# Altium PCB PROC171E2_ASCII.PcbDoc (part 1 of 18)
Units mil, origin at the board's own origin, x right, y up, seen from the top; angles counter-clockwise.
Board outline 7700 x 2300 mil, 6 copper layers (Top Layer, GND 1, SIG 1, SIG 2, GND 2, Bottom Layer), stack 61.062 mil thick; 938 components, 688 nets, 11933 pads, 1723 vias.
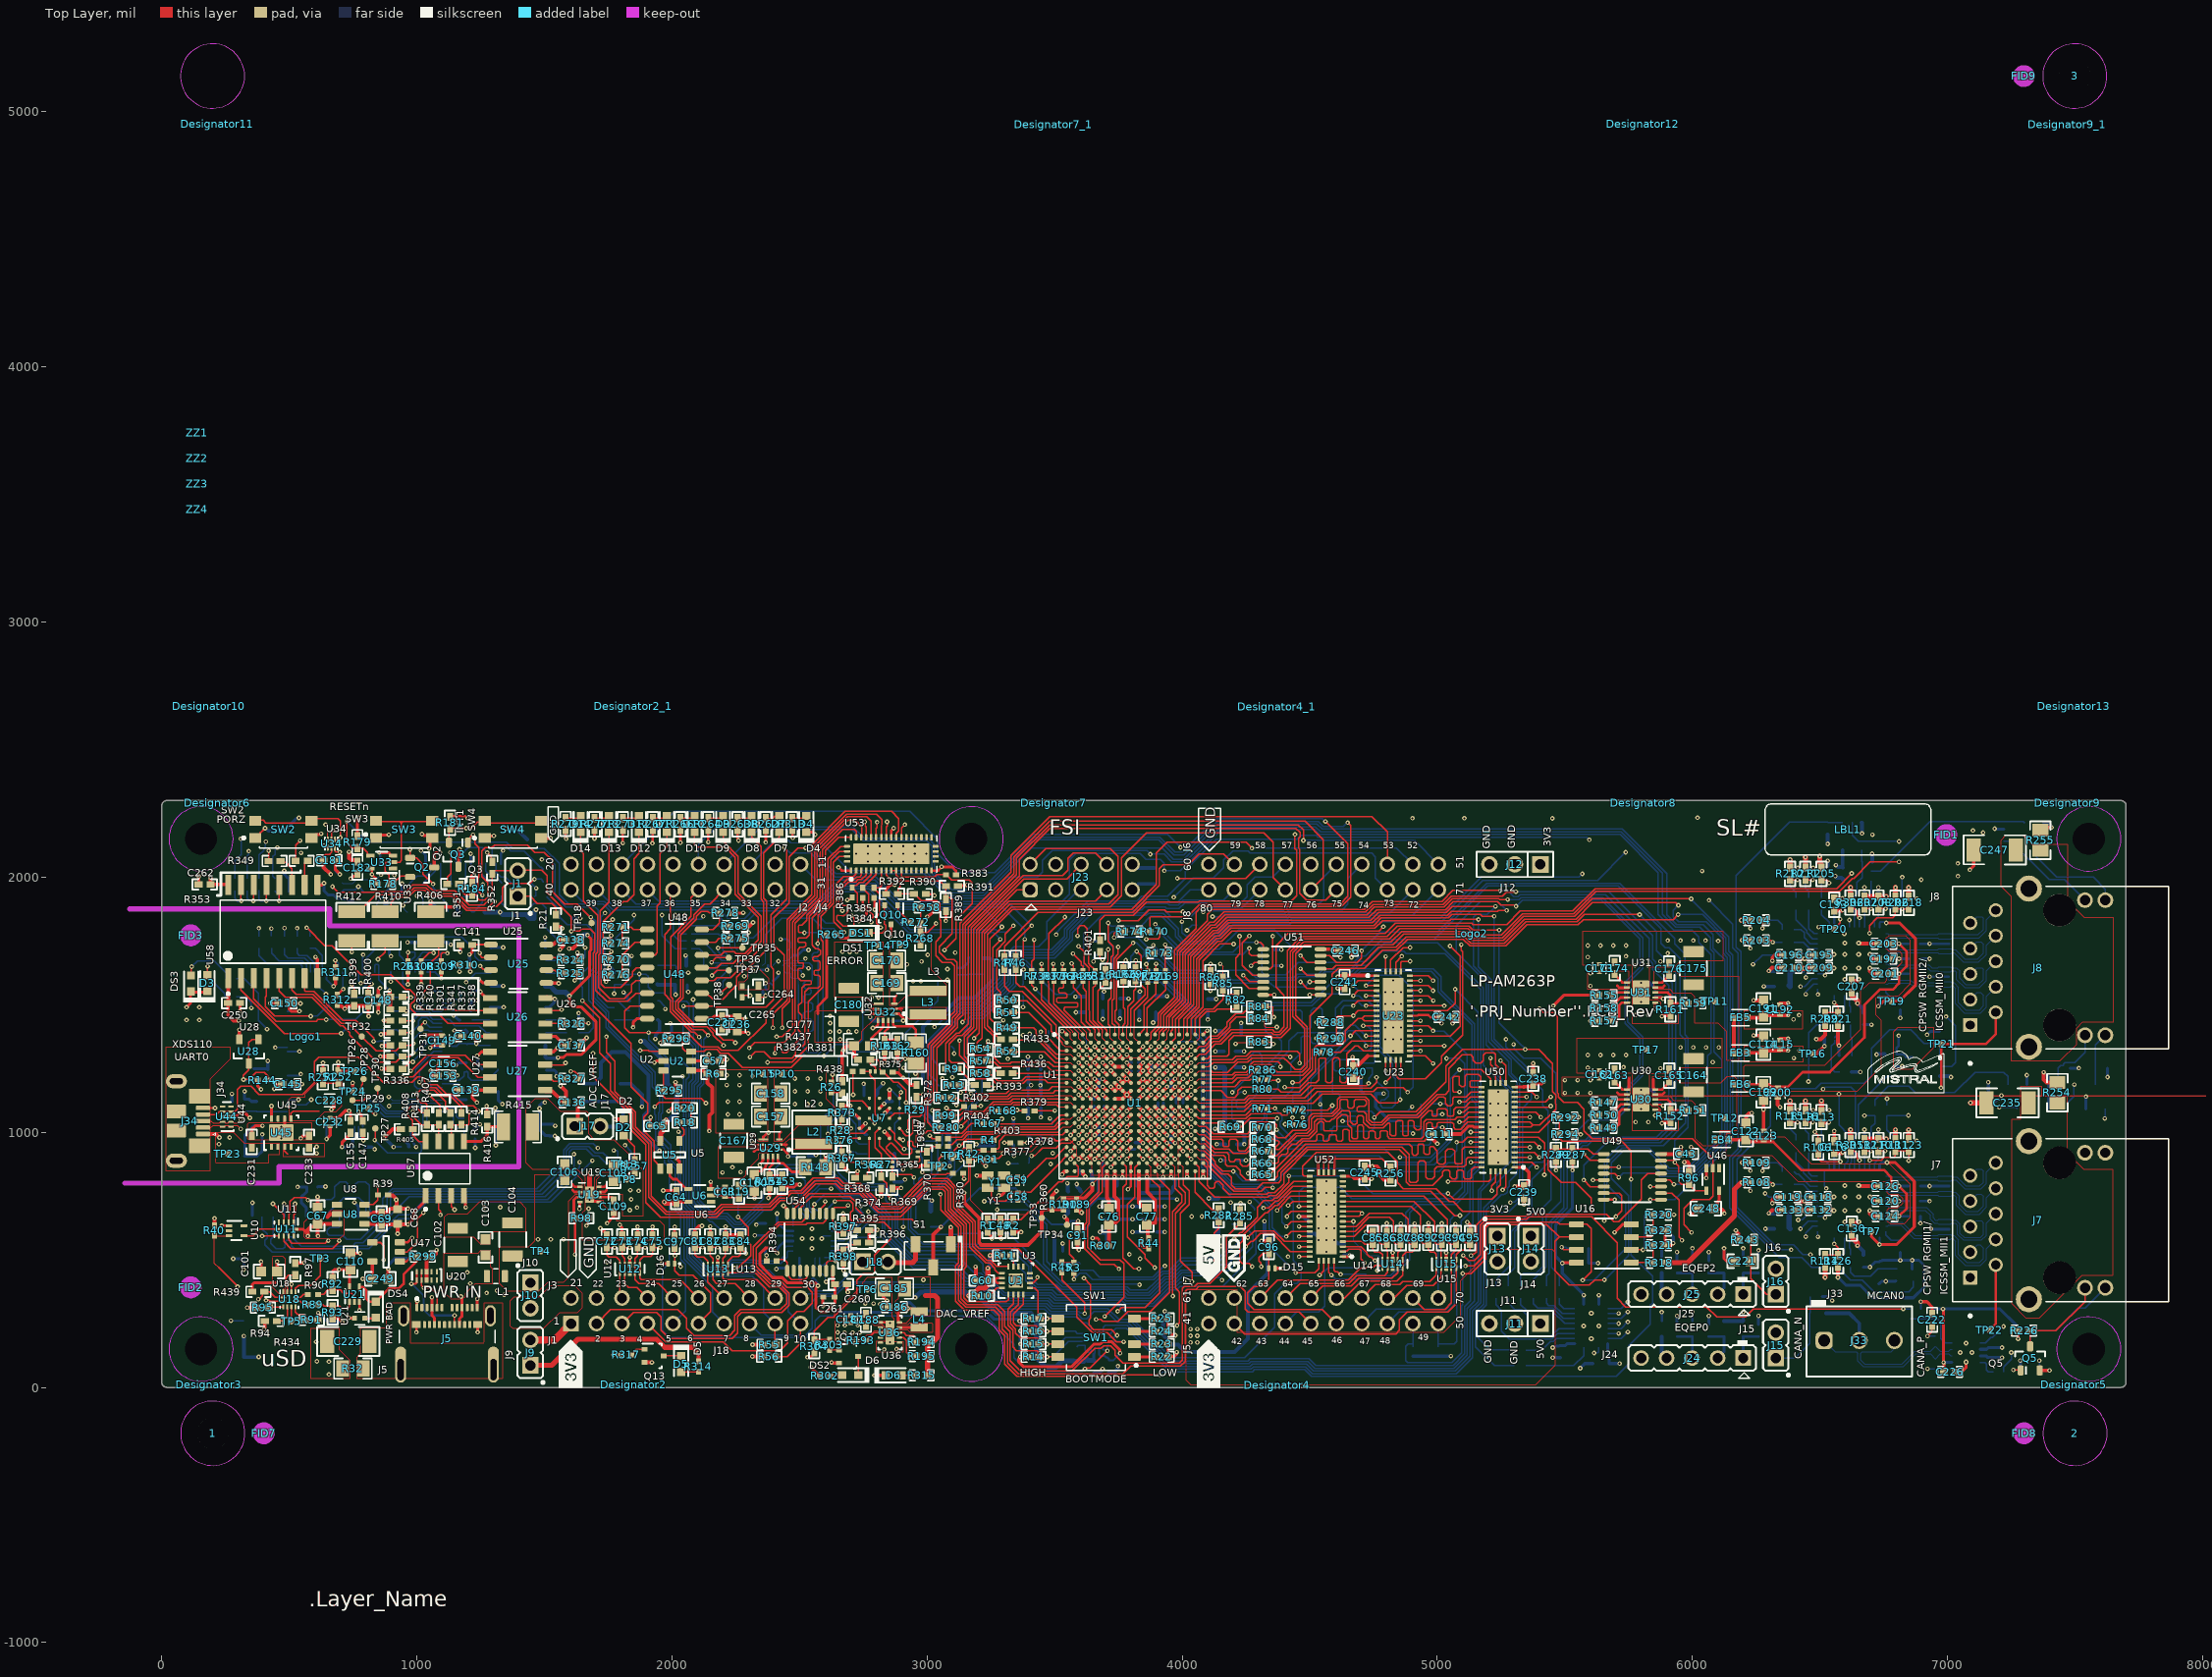
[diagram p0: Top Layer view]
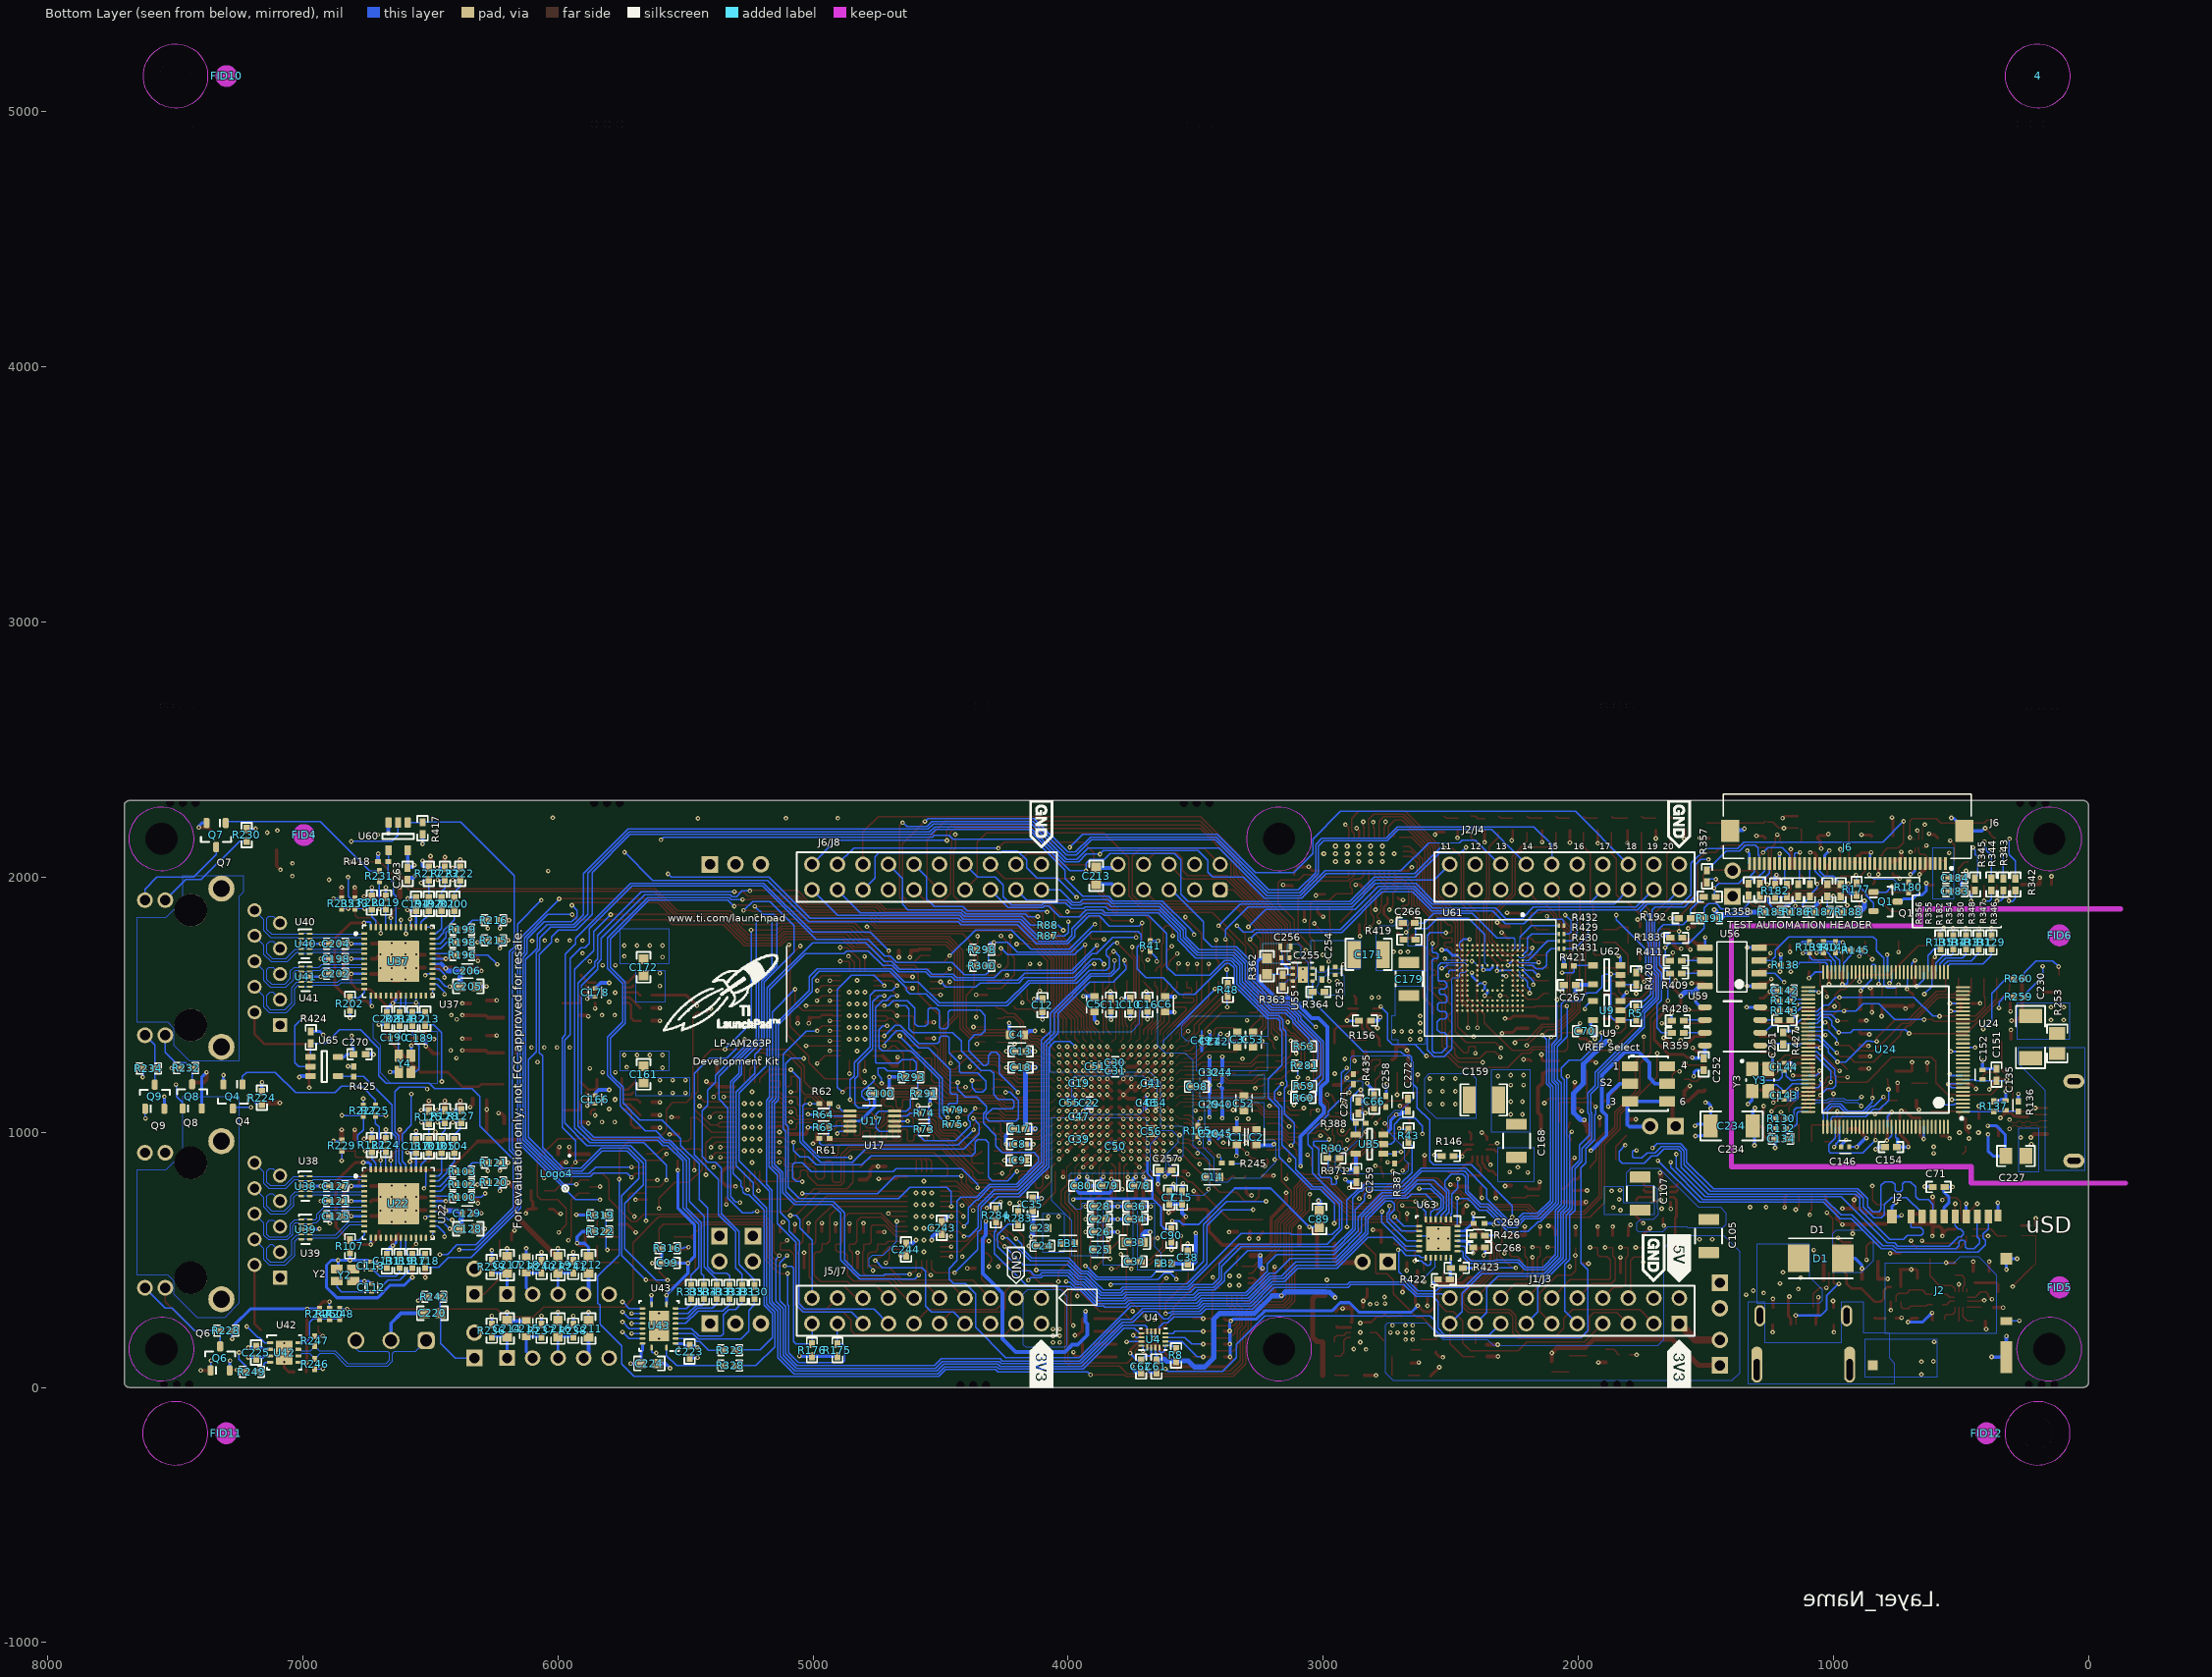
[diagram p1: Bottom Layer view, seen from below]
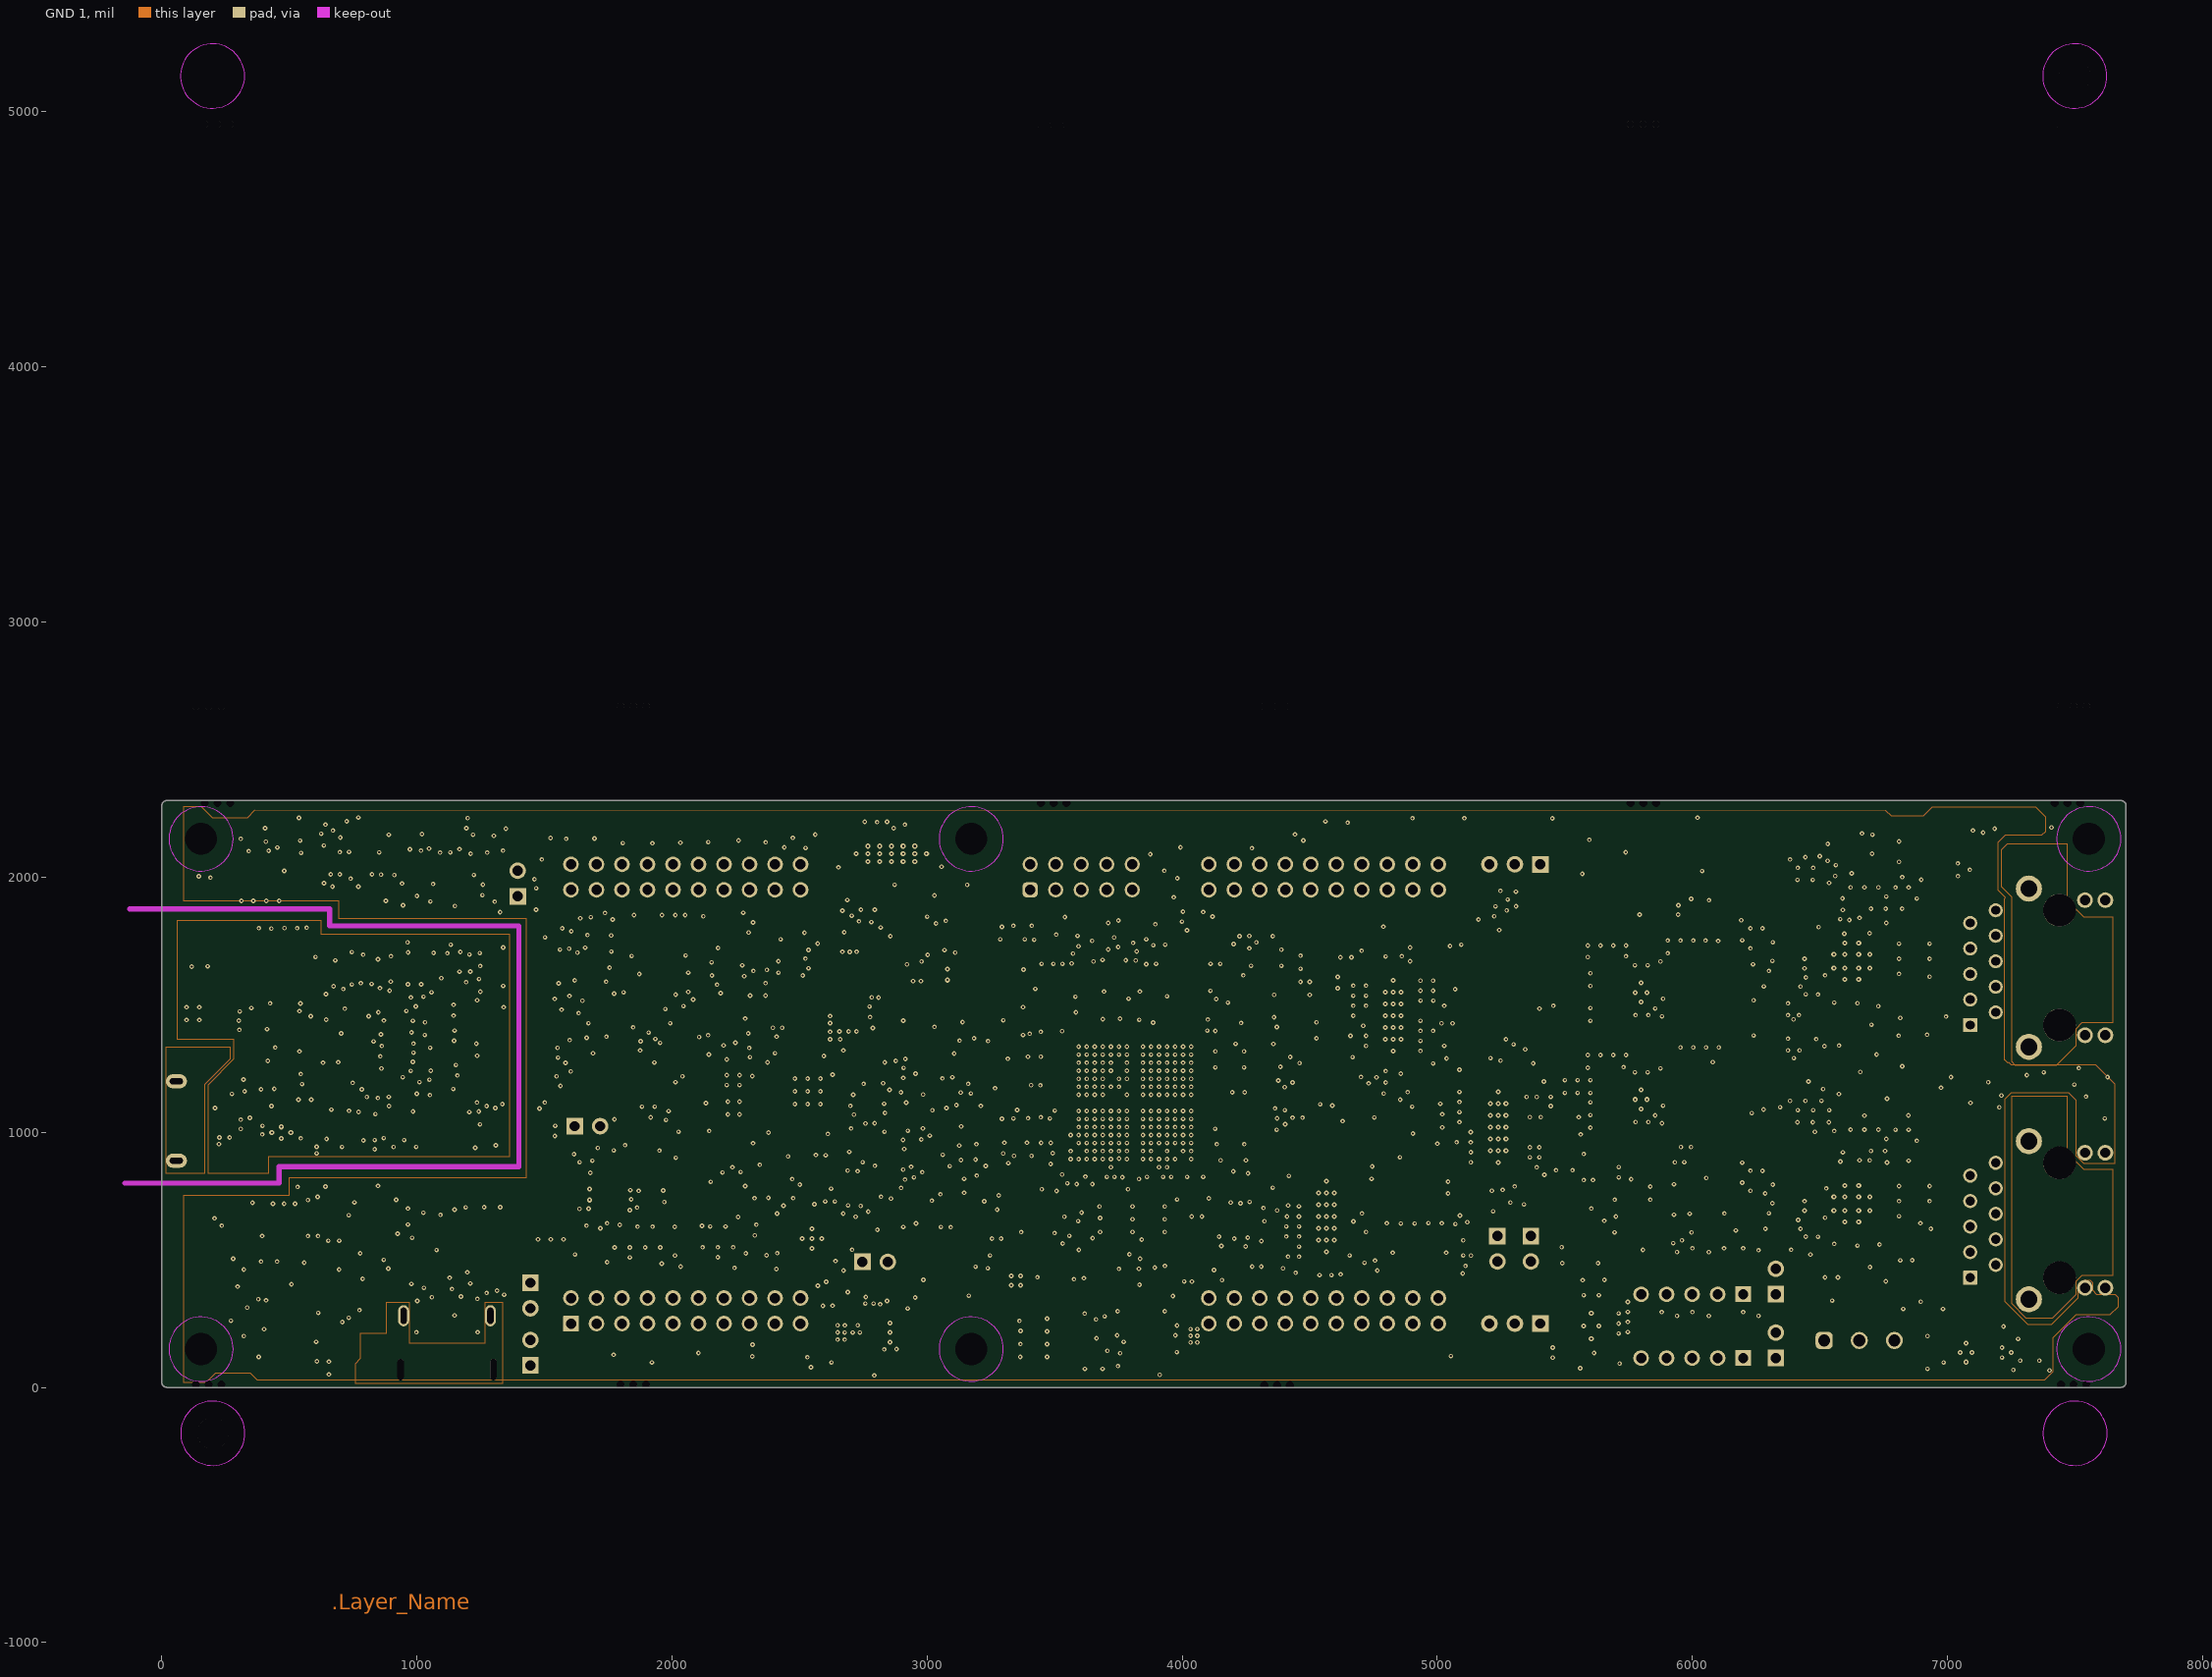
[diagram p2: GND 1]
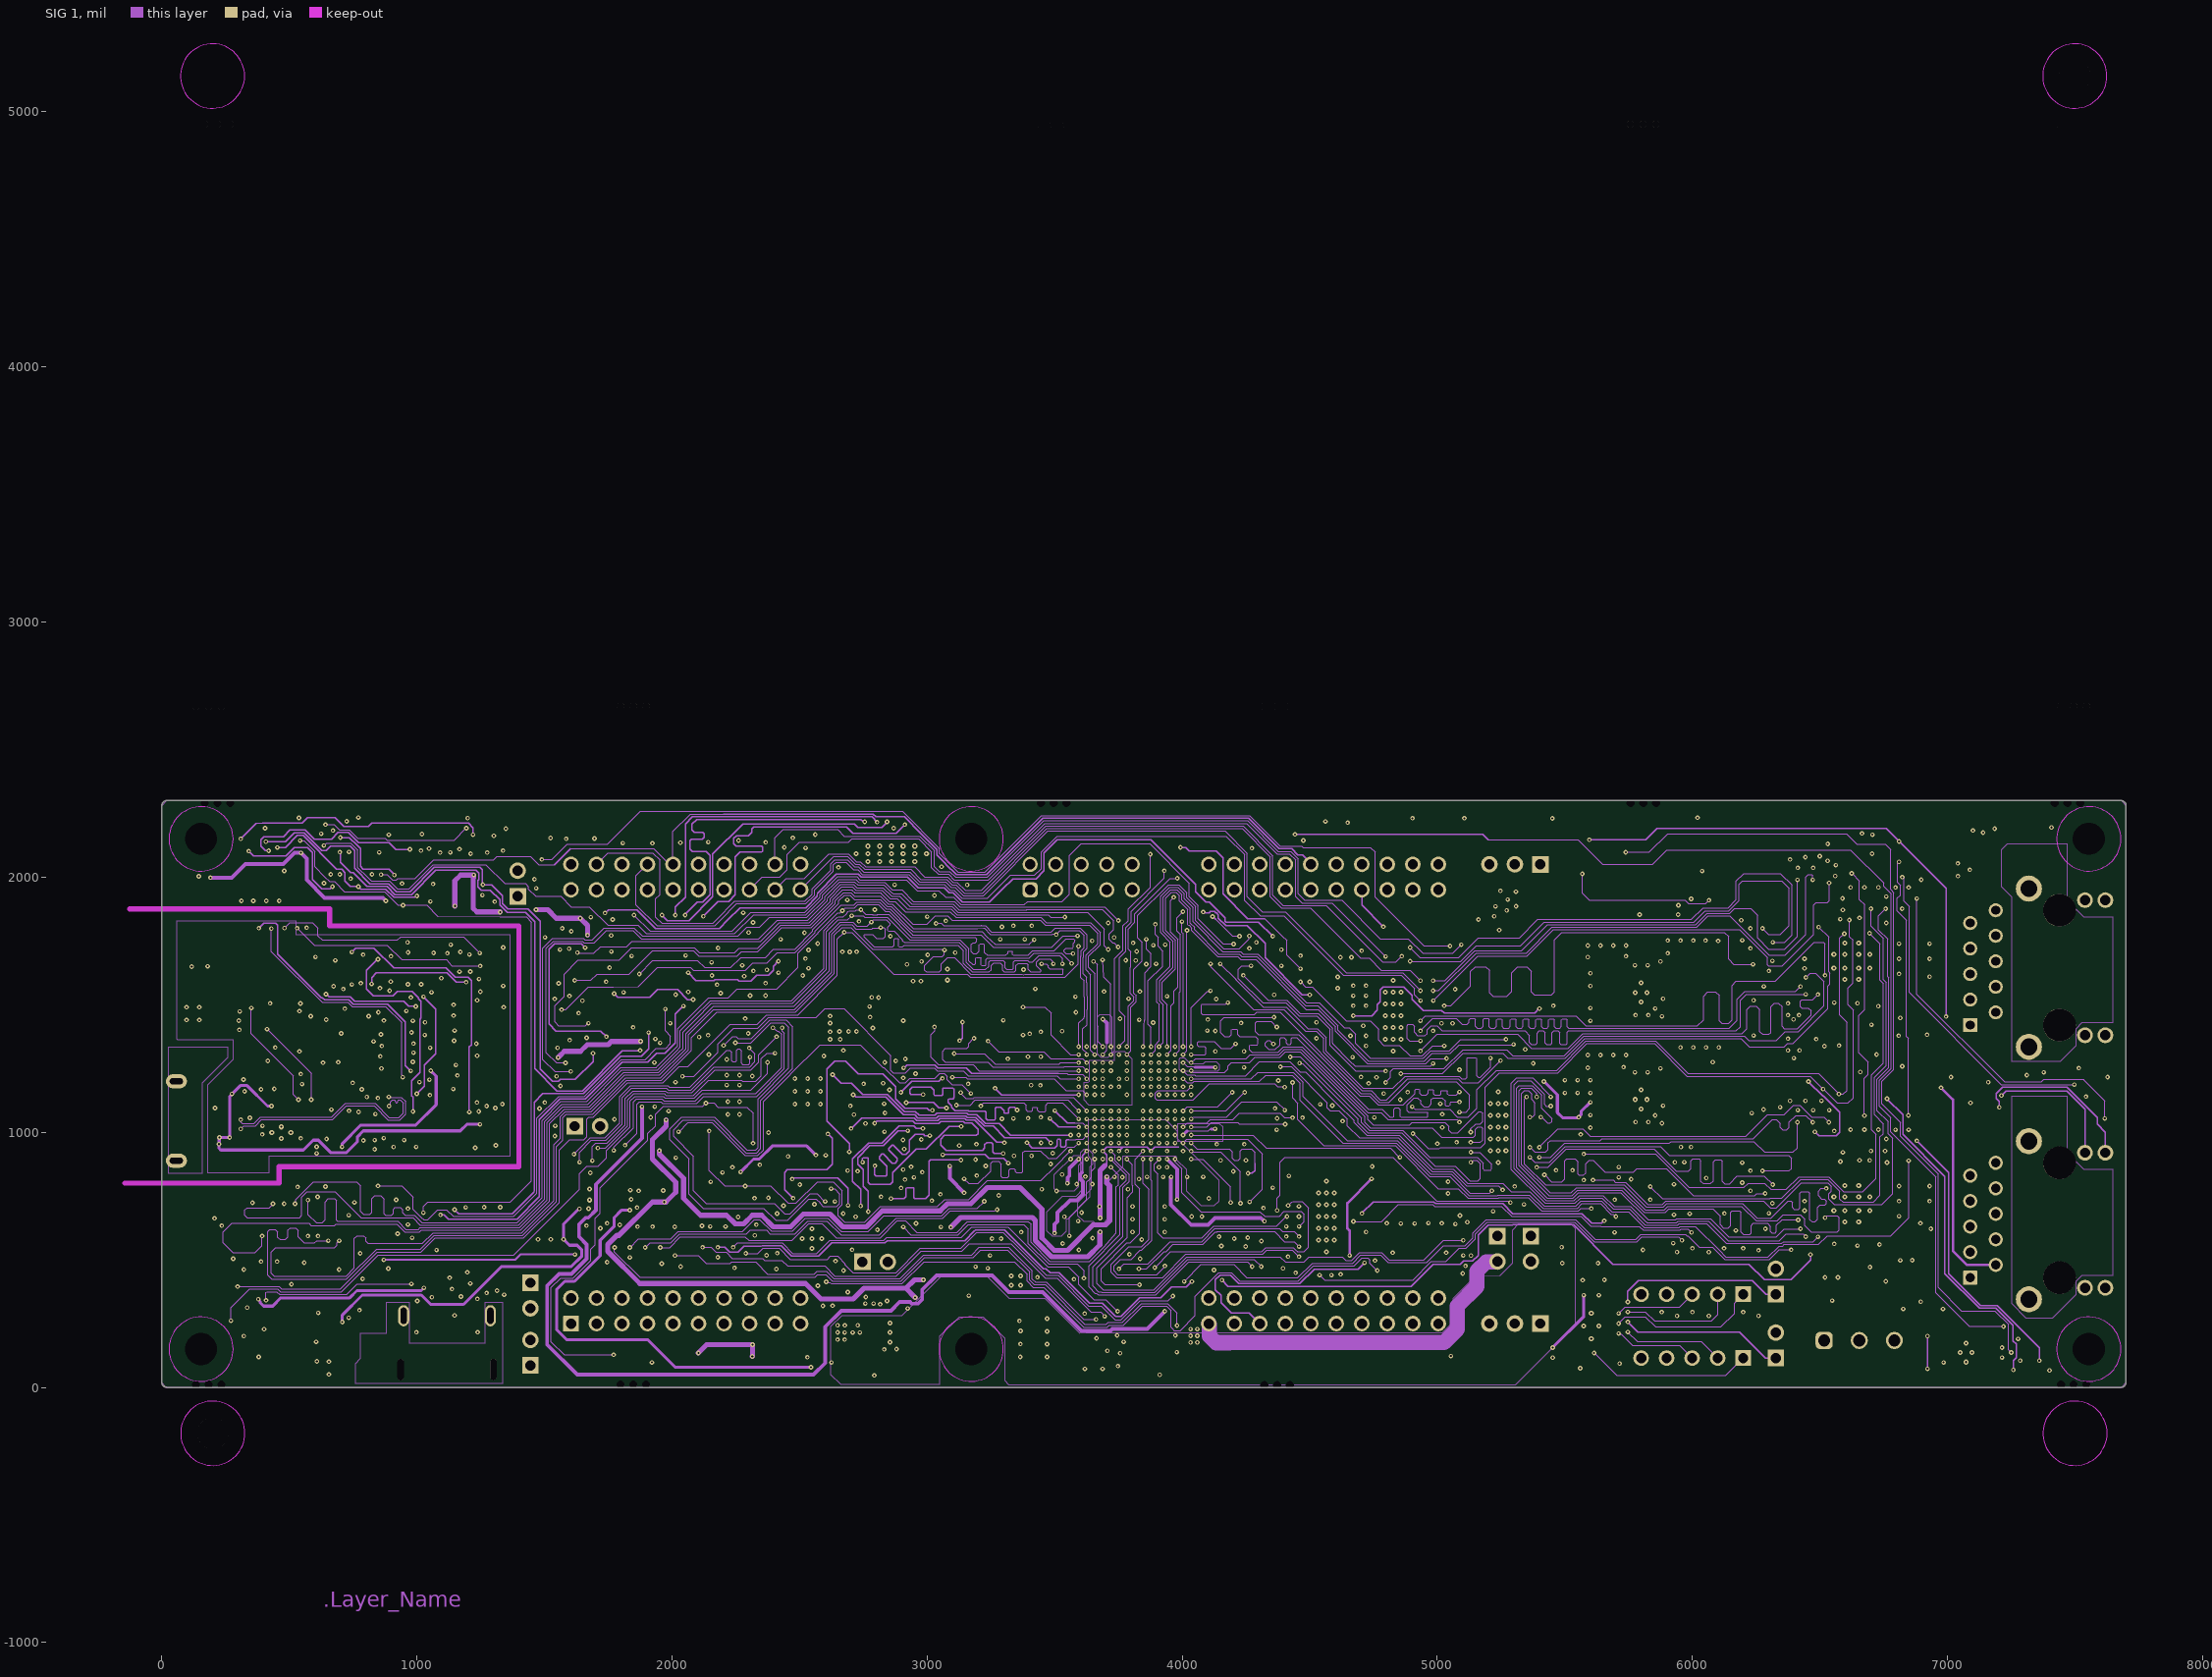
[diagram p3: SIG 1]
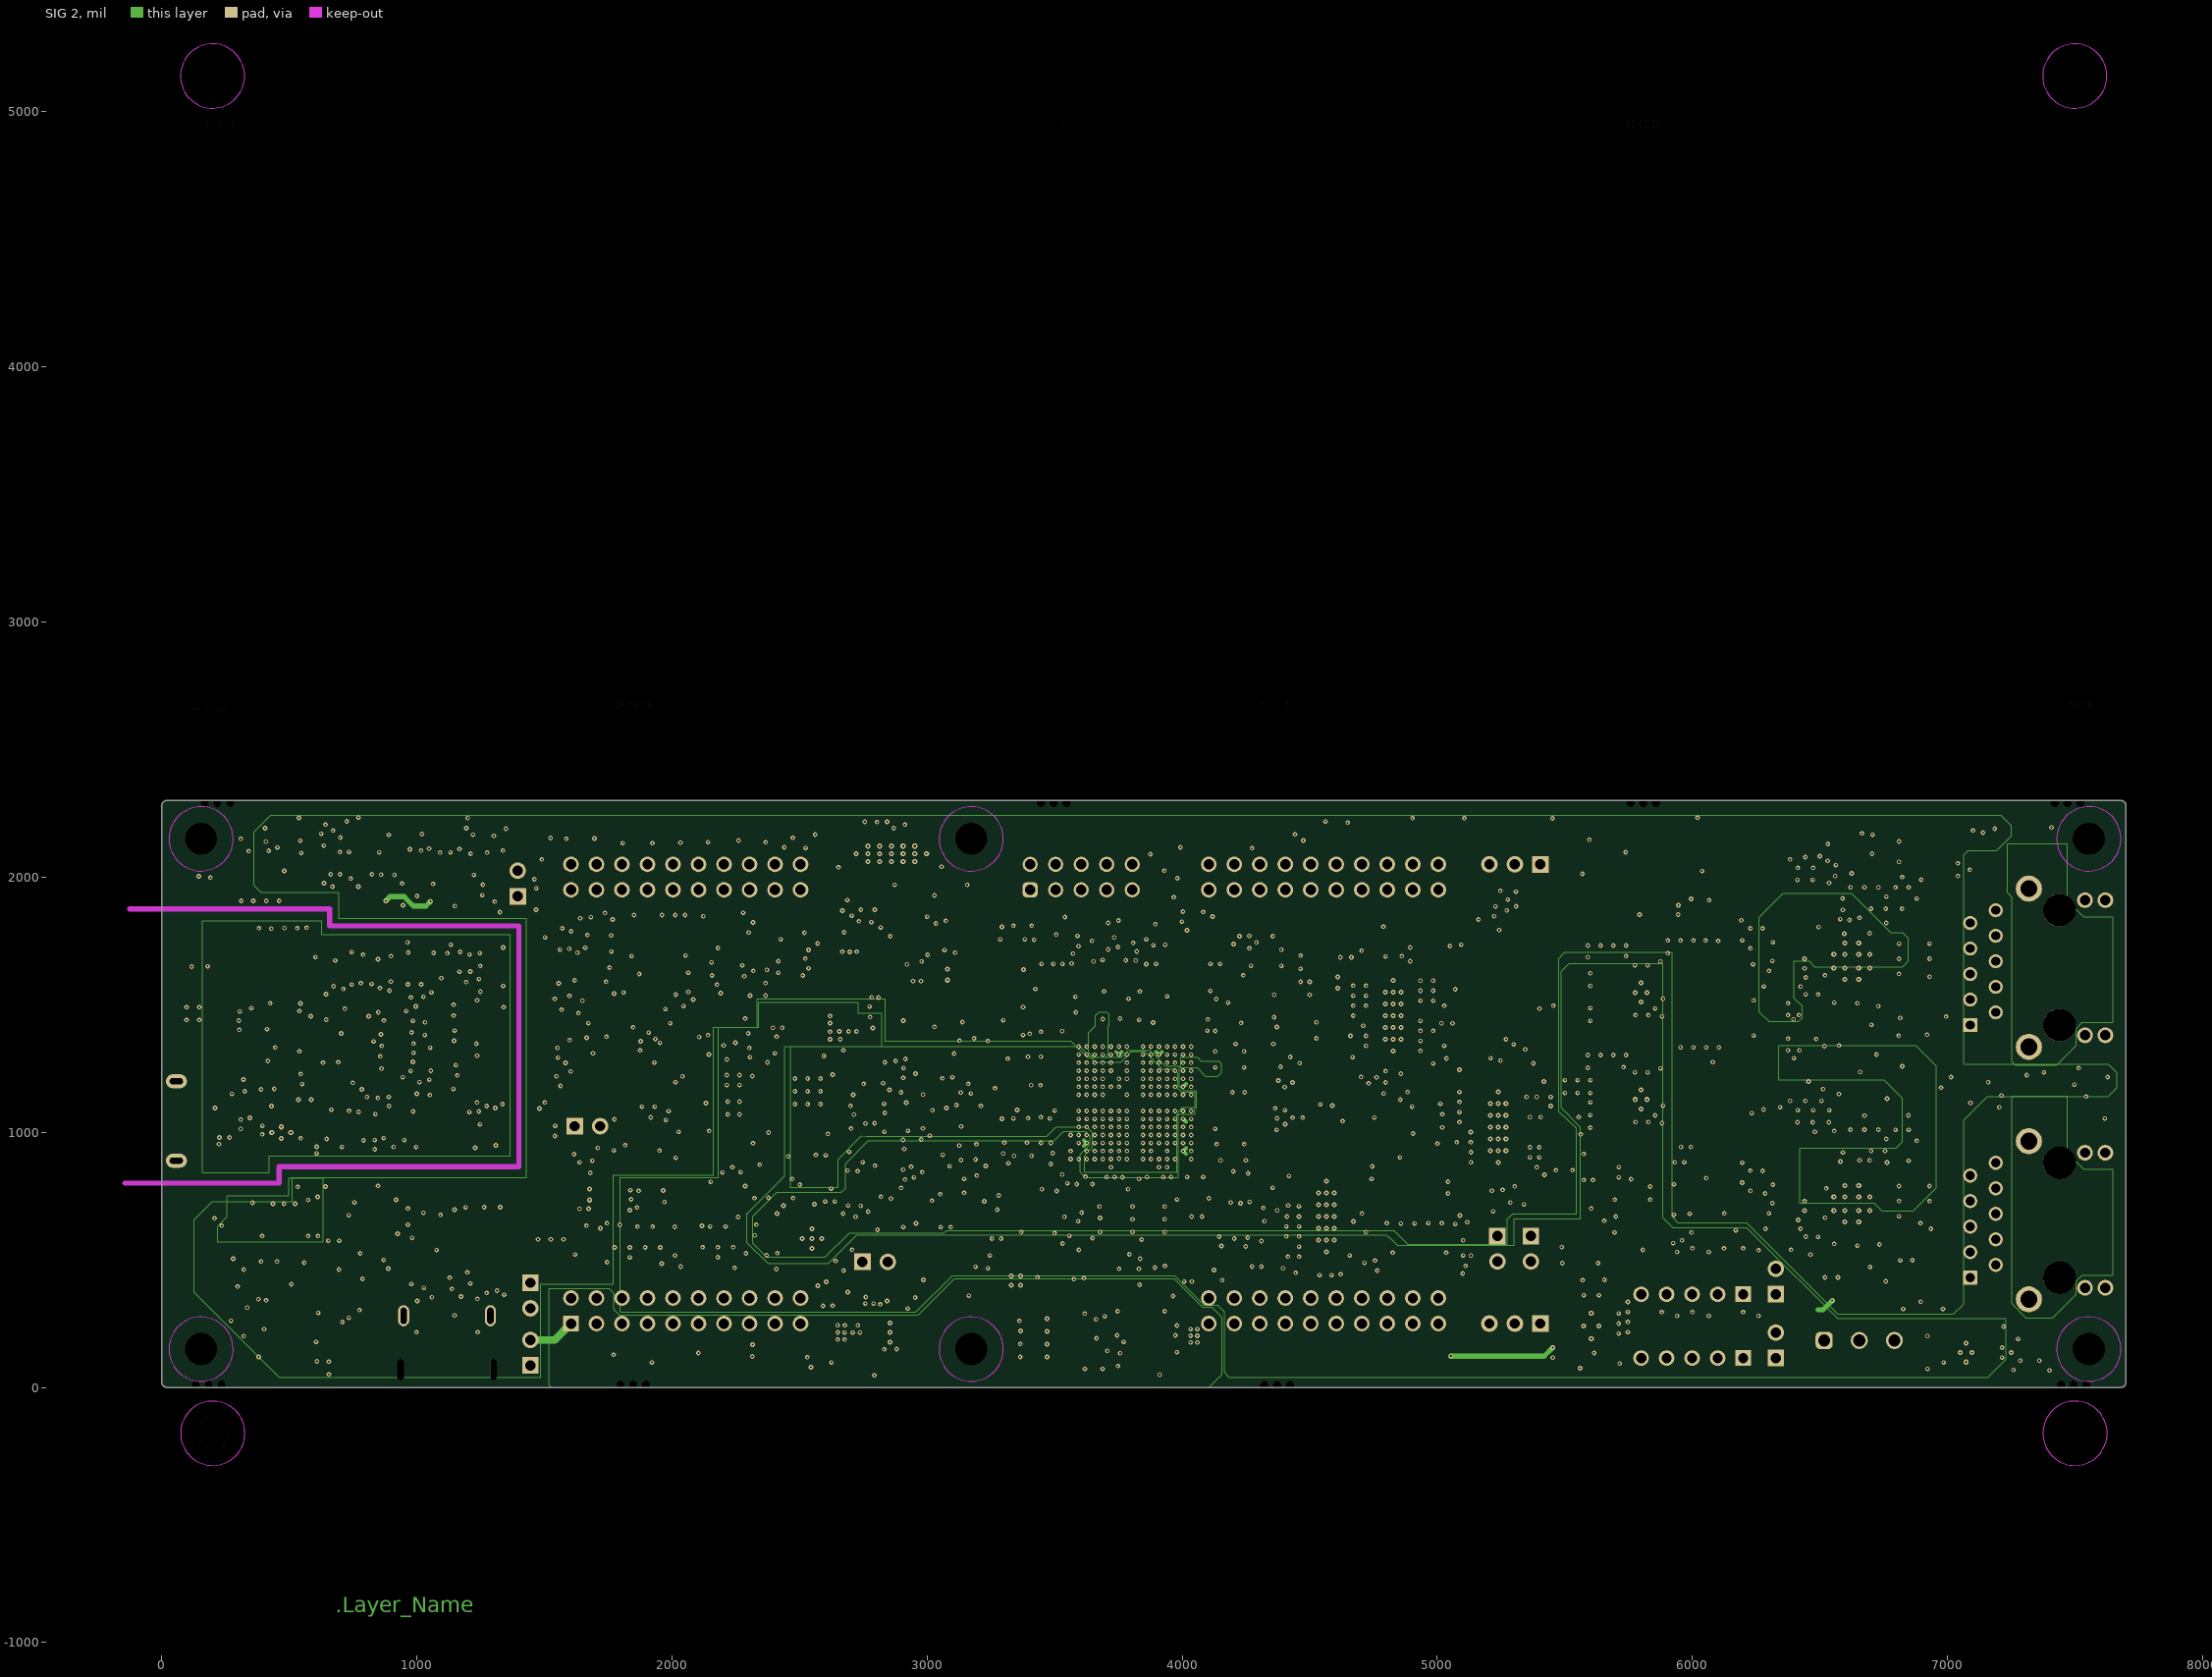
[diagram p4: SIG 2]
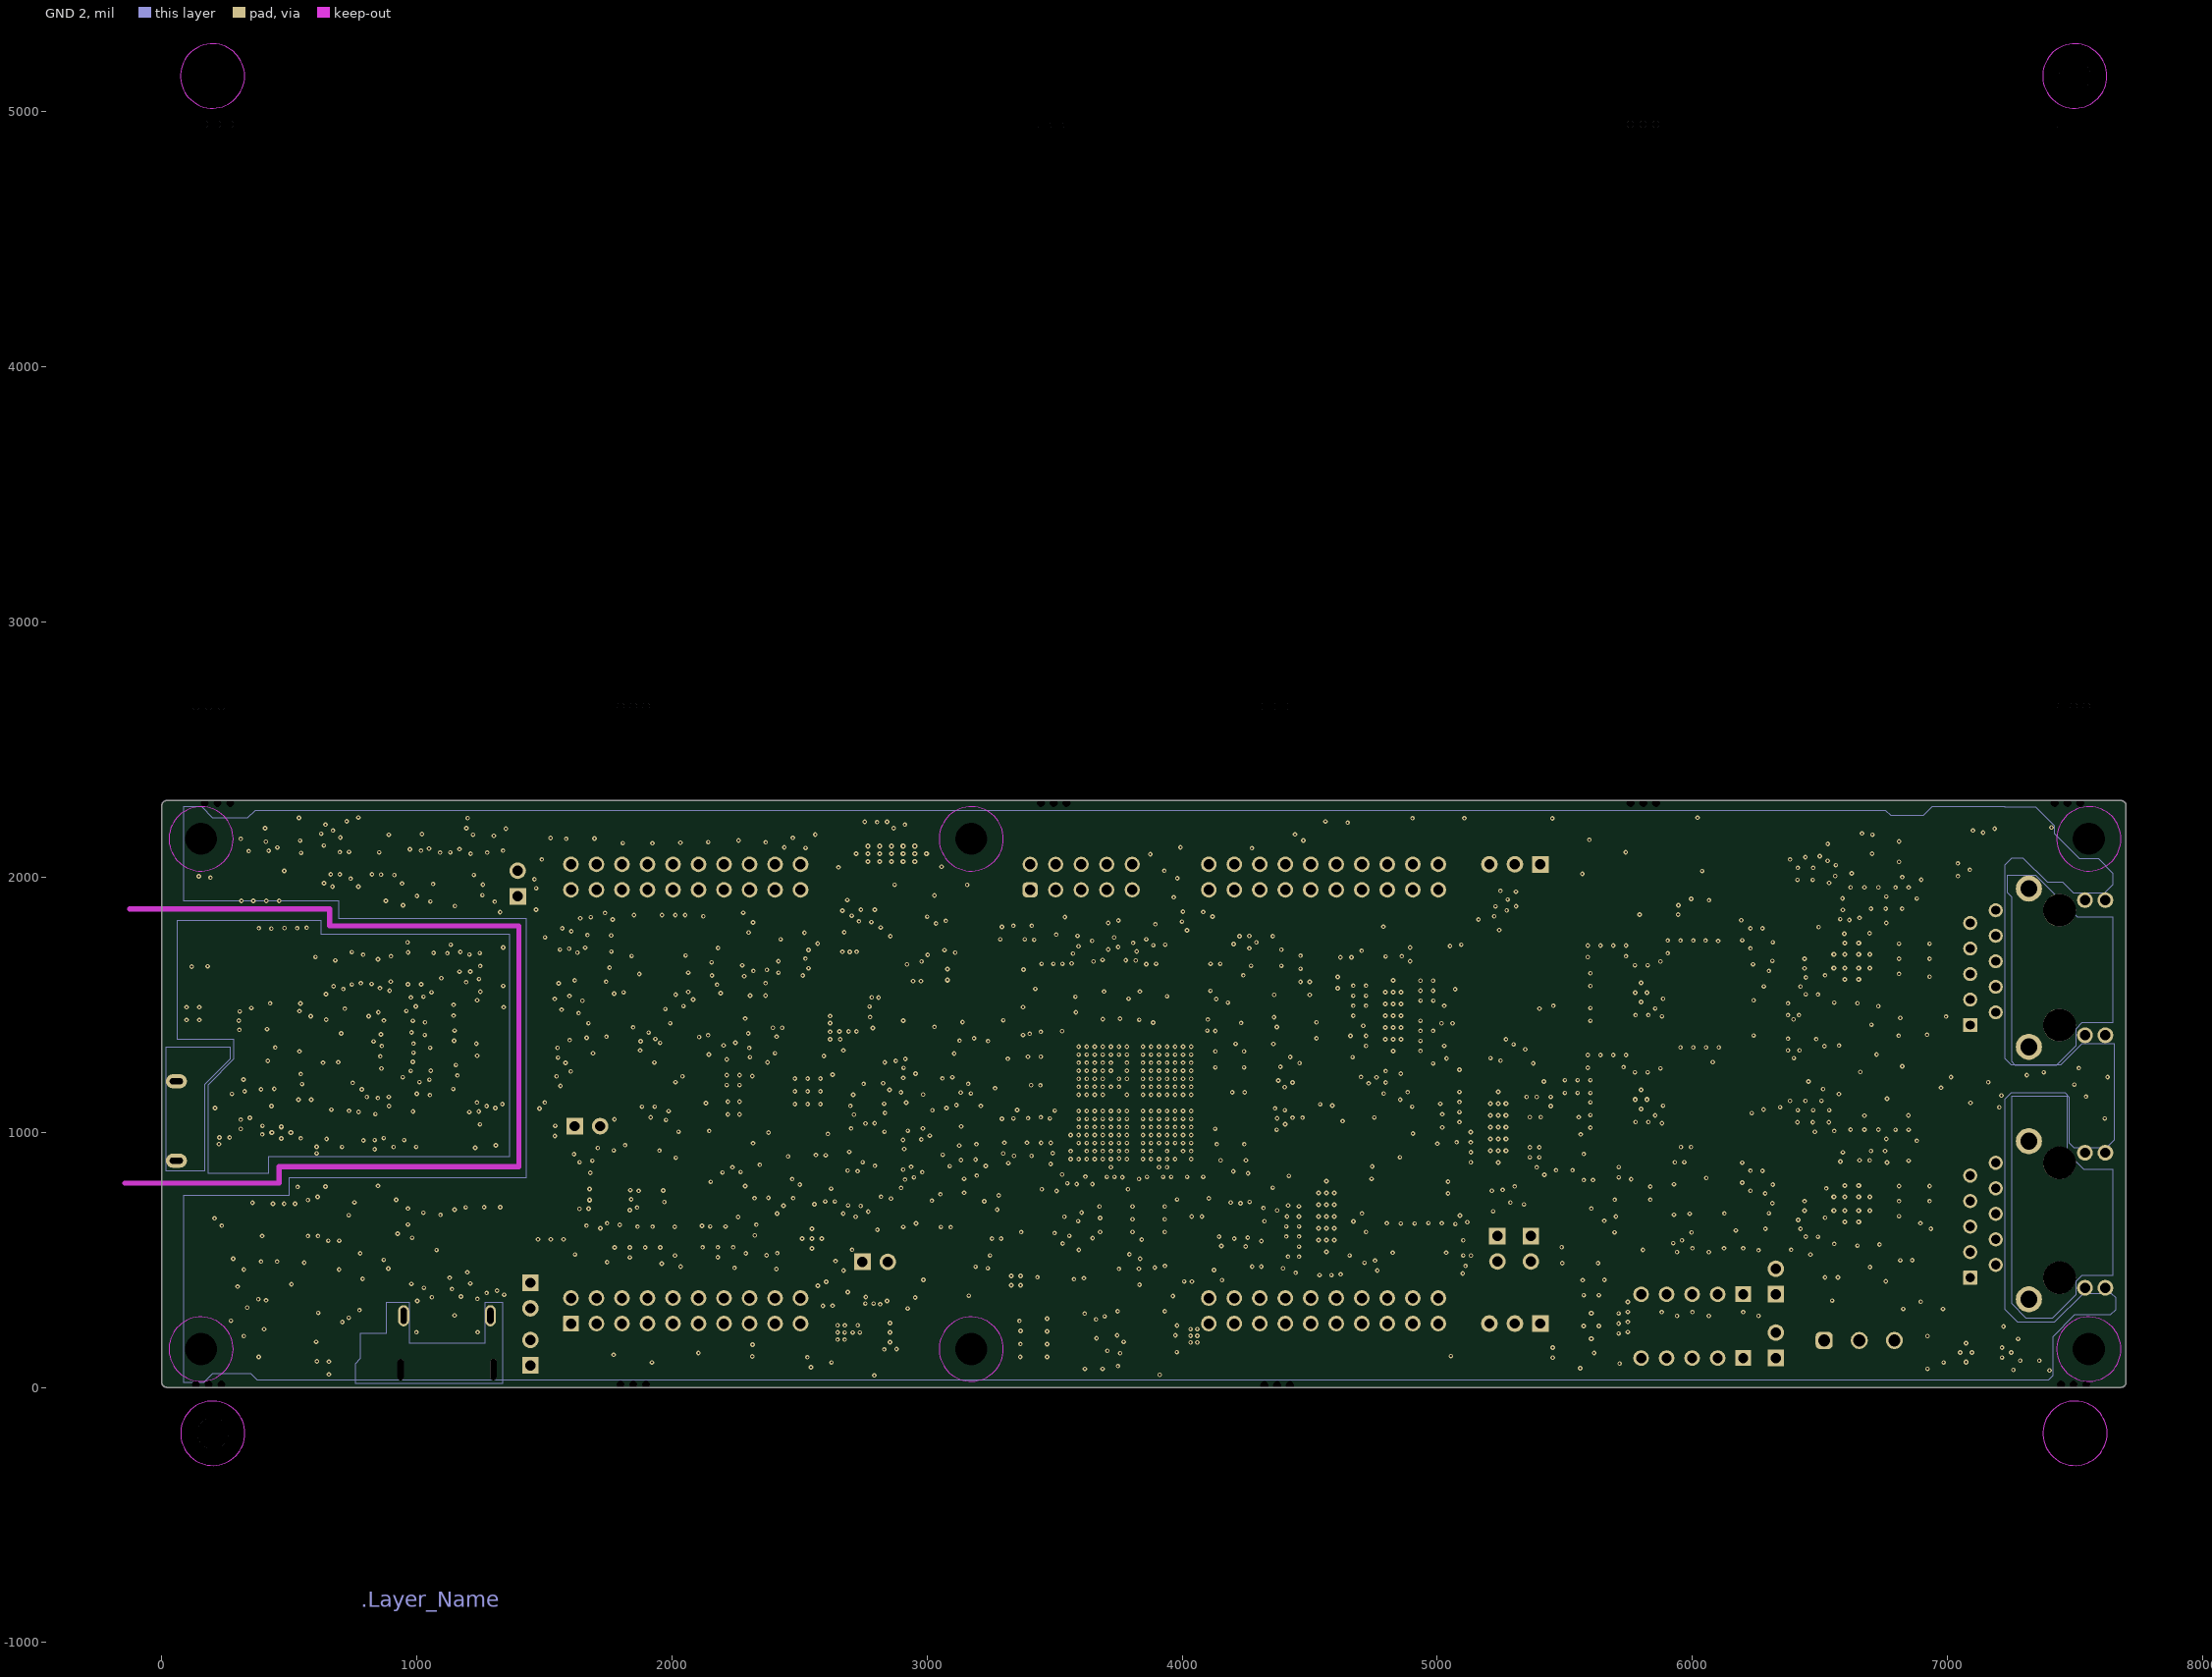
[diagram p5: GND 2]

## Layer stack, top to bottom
Top Solder: solder mask 1, Taiyo PSR 4000 HFX DI-GREEN, Dk 3.5
Top Layer: signal copper 2.087
Dielectric 1: prepreg 3.511, Iteq IT180A Prepreg 2113 RC58, Dk 4.13
GND 1: signal copper 1.26
Dielectric 3: core 4, Iteq IT180A 4 mil core 1/1, Dk 4.4
SIG 1: signal copper 1.26
Dielectric 5: core 1.75, Composite dielectric, Dk 3.79
Dielectric 6: core 2.663, Composite dielectric, Dk 3.79
Dielectric1: core 28, Composite dielectric, Dk 3.79
Dielectric 7: core 2.663, Composite dielectric, Dk 3.79
Dielectric 8: core 1.75, Composite dielectric, Dk 3.79
SIG 2: signal copper 1.26
Dielectric 4: core 4, Iteq IT180A 4 mil core 1/1, Dk 4.4
GND 2: signal copper 1.26
Dielectric 2: prepreg 3.511, Iteq IT180A Prepreg 2113 RC58, Dk 4.13
Bottom Layer: signal copper 2.087
Bottom Solder: solder mask 1, Taiyo PSR 4000 HFX DI-GREEN, Dk 3.5

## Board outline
0,20 0,2280 cw(c20,2280) 20,2300 7680,2300 cw(c7680,2280) 7700,2280 7700,20 cw(c7680,20) 7680,0 20,0 cw(c20,20)

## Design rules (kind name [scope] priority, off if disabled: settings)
AssemblyTestPointUsage [All] p0: scope1count=1 scope1_0_kind=Board scope1_0_value=Board scope2count=1 scope2_0_kind=Board scope2_0_value=Board commentlength=0
AssemblyTestPointUsage [All] p1: valid=2
AssemblyTestpoint [All] p0: scope1count=1 scope1_0_kind=Board scope1_0_value=Board scope2count=1 scope2_0_kind=Board scope2_0_value=Board commentlength=0
BoardOutlineClearance [All] p0 off: scope1count=1 scope1_0_kind=Board scope1_0_value=Board scope2count=1 scope2_0_kind=Board scope2_0_value=Board commentlength=172 gap=40 // Protel DXP Scope 1 Expression Was: OnCopper and Not InComponentClass('Logo') and not InComponentClass('FiducialMark') and not InRegion(1000,500,4000,800) and not InPoly
BoardOutlineClearance BoardOutlineClearance_Poly [All] p0 off: scope1count=1 scope1_0_kind=Board scope1_0_value=Board scope2count=1 scope2_0_kind=Board scope2_0_value=Board commentlength=58 gap=25 // Protel DXP Scope 1 Expression Was: OnCopper and IsPoly
BoardOutlineClearance BoardOutlineClearance_MountingHoles [All] p0 off: scope1count=1 scope1_0_kind=Board scope1_0_value=Board scope2count=1 scope2_0_kind=Board scope2_0_value=Board commentlength=86 gap=39.37 // Protel DXP Scope 1 Expression Was: OnCopper and InComponentClass('Mounting Holes')
BoardOutlineClearance BoardOutlineClearance_MountingHoles [OnCopper and InComponentClass('Mounting Holes')] p1: gap=39.37 ignorepadtopadclearanceinfootprint=FALSE
BoardOutlineClearance BoardOutlineClearance_Poly [OnCopper and IsPoly] p2: gap=25 ignorepadtopadclearanceinfootprint=FALSE
BoardOutlineClearance [OnCopper and Not InComponentClass('Logo') and not InComponentClass('FiducialMark') and not InRegion(1000,500,4000,800) and not InPoly] p3: gap=40 ignorepadtopadclearanceinfootprint=FALSE
Clearance FLASH-4mil [All] p0 off: scope1count=1 scope1_0_kind=Board scope1_0_value=Board scope2count=1 scope2_0_kind=Board scope2_0_value=Board commentlength=83 gap=3 // Protel DXP Scope 1 Expression Was: WithinRoom('FLASH - NAND') and OnBottomLayer
Clearance ADC_SIG1 [All] p0: scope1count=1 scope1_0_kind=Layer scope1_0_value=MID1 scope2count=1 scope2_0_kind=NetClass scope2_0_value=ADC0 commentlength=0 gap=7.87
Clearance ADC_EXT [All] p0 off: scope1count=1 scope1_0_kind=Board scope1_0_value=Board scope2count=1 scope2_0_kind=NetClass scope2_0_value=ADC0 commentlength=88 gap=7.87 // Protel DXP Scope 1 Expression Was: (OnLayer('Top Layer') or OnLayer('Bottom Layer'))
Clearance DIff_spacing [All] p0 off: scope1count=1 scope1_0_kind=Board scope1_0_value=Board scope2count=1 scope2_0_kind=Board scope2_0_value=Board commentlength=70 gap=7.87 // Protel DXP Scope 2 Expression Was: InDifferentialPair('XDSET_1_D')
Clearance 100E_CLR_same [All] p0 off: scope1count=1 scope1_0_kind=Board scope1_0_value=Board scope2count=1 scope2_0_kind=Board scope2_0_value=Board commentlength=70 gap=7.87 // Protel DXP Scope 1 Expression Was: InDifferentialPairClass('100E')
Clearance 100E_CLR [All] p0 off: scope1count=1 scope1_0_kind=Board scope1_0_value=Board scope2count=1 scope2_0_kind=Board scope2_0_value=Board commentlength=70 gap=7.87 // Protel DXP Scope 1 Expression Was: InDifferentialPairClass('100E')
Clearance 4mil [All] p0 off: scope1count=1 scope1_0_kind=Board scope1_0_value=Board scope2count=1 scope2_0_kind=Board scope2_0_value=Board commentlength=69 gap=4 // Protel DXP Scope 1 Expression Was: WithinRoom('PROC111_Hardware')
Clearance [All] p0: scope1count=1 scope1_0_kind=Board scope1_0_value=Board scope2count=1 scope2_0_kind=Board scope2_0_value=Board commentlength=0 gap=7.87
Clearance Clearance_Poly [All] p0 off: scope1count=1 scope1_0_kind=Board scope1_0_value=Board scope2count=1 scope2_0_kind=Board scope2_0_value=Board commentlength=48 gap=10 // Protel DXP Scope 1 Expression Was: InPolygon
Clearance Clearance_Keepouts [All] p0 off: scope1count=1 scope1_0_kind=Board scope1_0_value=Board scope2count=1 scope2_0_kind=Board scope2_0_value=Board commentlength=48 gap=1 // Protel DXP Scope 1 Expression Was: IsKeepOut
Clearance FLASH-4mil [WithinRoom('FLASH - NAND') and OnBottomLayer] p1: gap=3 ignorepadtopadclearanceinfootprint=TRUE except(3.4: Arc-SMDPad Track-SMDPad; 15: Fill-Fill Fill-Poly Fill-Region Poly-Poly Poly-Region Region-Region)
Clearance Clearance_Keepouts [IsKeepOut] p2: gap=1 ignorepadtopadclearanceinfootprint=FALSE
Clearance 4mil [WithinRoom('PROC111_Hardware')] p3: gap=4 ignorepadtopadclearanceinfootprint=TRUE except(15: Fill-Fill Fill-Poly Fill-Region Poly-Poly Poly-Region Region-Region)
Clearance ADC_EXT [(OnLayer('Top Layer') or OnLayer('Bottom Layer')) vs InNetClass('ADC0')] p4: gap=7.87 ignorepadtopadclearanceinfootprint=TRUE except(6: Via-Fill Via-Poly Via-Region; 10.6: Arc-Arc Arc-Track Track-Track; 18: Via-Via; 25: Fill-Fill Fill-Poly Fill-Region Poly-Poly Poly-Region Region-Region)
Clearance ADC_SIG1 [OnLayer('SIG 1') vs InNetClass('ADC0')] p5: gap=7.87 ignorepadtopadclearanceinfootprint=TRUE except(6: Via-Fill Via-Poly Via-Region; 9.5: Arc-Arc Arc-Track Track-Track; 18: Via-Via; 25: Fill-Fill Fill-Poly Fill-Region Poly-Poly Poly-Region Region-Region)
Clearance 100E_CLR_same [InDifferentialPairClass('100E')] p6: gap=7.87 ignorepadtopadclearanceinfootprint=TRUE except(7.7: Arc-Arc Arc-Track Track-Track; 10: Via-Fill Via-Poly Via-Region; 18: Via-Via; 25: Fill-Fill Fill-Poly Fill-Region Poly-Poly Poly-Region Region-Region)
Clearance 100E_CLR [InDifferentialPairClass('100E')] p7: gap=7.87 ignorepadtopadclearanceinfootprint=TRUE except(6: Via-Fill Via-Poly Via-Region; 16.2: Arc-Arc Arc-Track Track-Track; 18: Via-Via; 25: Fill-Fill Fill-Poly Fill-Region Poly-Poly Poly-Region Region-Region)
Clearance Clearance_Poly [InPolygon] p8: gap=10 ignorepadtopadclearanceinfootprint=TRUE except(6: Via-Fill Via-Poly Via-Region; 8: SMDPad-Fill SMDPad-Poly SMDPad-Region THPad-Fill THPad-Poly THPad-Region; 20: Fill-Fill Fill-Poly Fill-Region Poly-Poly Poly-Region Region-Region)
Clearance DIff_spacing [All vs InDifferentialPair('XDSET_1_D')] p9: gap=7.87 ignorepadtopadclearanceinfootprint=TRUE except(5: Arc-Arc Arc-Track Track-Track; 6: Via-Fill Via-Poly Via-Region; 18: Via-Via; 25: Fill-Fill Fill-Poly Fill-Region Poly-Poly Poly-Region Region-Region)
Clearance [All] p10: gap=7.87 ignorepadtopadclearanceinfootprint=TRUE except(5.3: Arc-Arc Arc-Track Track-Track; 6: SMDPad-SMDPad Via-Fill Via-Poly Via-Region; 7.4: Arc-SMDPad Track-SMDPad; 12: Via-Via; 25: Fill-Fill Fill-Poly Fill-Region Poly-Poly Poly-Region Region-Region)
ComponentClearance [All] p0: scope1count=1 scope1_0_kind=Board scope1_0_value=Board scope2count=1 scope2_0_kind=Board scope2_0_value=Board commentlength=0 gap=15 collisioncheckmode=3
ComponentClearance ComponentClearance_THtoTH [All] p0 off: scope1count=1 scope1_0_kind=Board scope1_0_value=Board scope2count=1 scope2_0_kind=Board scope2_0_value=Board commentlength=54 gap=20 collisioncheckmode=3 // Protel DXP Scope 2 Expression Was: IsThruComponent
ComponentClearance ComponentClearance_THtoSMT [All] p0 off: scope1count=1 scope1_0_kind=Board scope1_0_value=Board scope2count=1 scope2_0_kind=Board scope2_0_value=Board commentlength=53 gap=30 collisioncheckmode=3 // Protel DXP Scope 2 Expression Was: IsSMTComponent
ComponentClearance ComponentClearance_SmallPassives [All] p0 off: scope1count=1 scope1_0_kind=Board scope1_0_value=Board scope2count=1 scope2_0_kind=Board scope2_0_value=Board commentlength=508 gap=10 collisioncheckmode=3 // Protel DXP Scope 2 Expression Was: HasFootprint('0201*') or HasFootprint('0402*') or HasFootprint('0508') or HasFootprint('0603*') or HasFootprint('0612') or HasFootprint('0805*') or HasFootprint('0815*') or HasFootprint('0830*') or HasFootprint('1206*') or HasFootprint('1210*') or HasFootprint('1808*') or HasFootprint('1812*') or HasFootprint('1825*') or HasFootprint('2010*') or HasFootprint('2220*') or HasFootprint('2225*') or HasFootprint('2512*') or HasFootprint('2728*') or HasFootprint('3518*')
ComponentClearance ComponentClearance_MountingHoles [All] p0: scope1count=1 scope1_0_kind=ComponentClass scope1_0_value="Mounting Holes" scope2count=1 scope2_0_kind=Board scope2_0_value=Board commentlength=0 gap=100 collisioncheckmode=3
ComponentClearance ComponentClearance_ScrewToNut [All] p0 off: scope1count=1 scope1_0_kind=Board scope1_0_value=Board scope2count=1 scope2_0_kind=Board scope2_0_value=Board commentlength=71 gap=5 collisioncheckmode=3 // Protel DXP Scope 2 Expression Was: (HasFootprint('Keystone_1902C'))
ComponentClearance ComponentClearance_Logo [All] p0: scope1count=1 scope1_0_kind=ComponentClass scope1_0_value=Logo scope2count=1 scope2_0_kind=Board scope2_0_value=Board commentlength=0 gap=30 collisioncheckmode=3
ComponentClearance ComponentClearance_Shunt [All] p0: scope1count=1 scope1_0_kind=ComponentClass scope1_0_value=Header scope2count=1 scope2_0_kind=ComponentClass scope2_0_value=Shunt commentlength=0 gap=0 collisioncheckmode=3
ComponentClearance ComponentClearance_MountingHoles_FiducialMarks [All] p0: scope1count=1 scope1_0_kind=ComponentClass scope1_0_value="Mounting Holes" scope2count=1 scope2_0_kind=ComponentClass scope2_0_value=FiducialMark commentlength=0 gap=50 collisioncheckmode=3
ComponentClearance ComponentClearance_MountingHoles_FiducialMarks [InComponentClass('Mounting Holes') vs InComponentClass('FiducialMark')] p1: gap=50 collisioncheckmode=3 verticalgap=10 showdistances=FALSE
ComponentClearance ComponentClearance_Shunt [InComponentClass('Header') vs InComponentClass('Shunt')] p2: gap=0 collisioncheckmode=3 verticalgap=0 showdistances=FALSE
ComponentClearance ComponentClearance_Logo [InComponentClass('Logo')] p3: gap=30 collisioncheckmode=3 verticalgap=10 showdistances=FALSE
ComponentClearance ComponentClearance_ScrewToNut [(HasFootprint('NY PMS 440 0025 PH')) vs (HasFootprint('Keystone_1902C'))] p4: gap=5 collisioncheckmode=3 verticalgap=10 showdistances=FALSE
ComponentClearance ComponentClearance_MountingHoles [InComponentClass('Mounting Holes')] p5: gap=100 collisioncheckmode=3 verticalgap=100000 showdistances=FALSE
ComponentClearance ComponentClearance_SmallPassives [HasFootprint('0201*') or HasFootprint('0402*') or HasFootprint('0508') or HasFootprint('0603*') or HasFootprint('0612') or HasFootprint('0805*') or HasFootprint('0815*') or HasFootprint('0830*') or HasFootprint('1206*') or HasFootprint('1210*') or HasFootprint('1808*') or HasFootprint('1812*') or HasFootprint('1825*') or HasFootprint('2010*') or HasFootprint('2220*') or HasFootprint('2225*') or HasFootprint('2512*') or HasFootprint('2728*') or HasFootprint('3518*') vs HasFootprint('0201*') or HasFootprint('0402*') or HasFootprint('0508') or HasFootprint('0603*') or HasFootprint('0612') or HasFootprint('0805*') or HasFootprint('0815*') or HasFootprint('0830*') or HasFootprint('1206*') or HasFootprint('1210*') or HasFootprint('1808*') or HasFootprint('1812*') or HasFootprint('1825*') or HasFootprint('2010*') or HasFootprint('2220*') or HasFootprint('2225*') or HasFootprint('2512*') or HasFootprint('2728*') or HasFootprint('3518*')] p6: gap=10 collisioncheckmode=3 verticalgap=10 showdistances=FALSE
ComponentClearance ComponentClearance_THtoSMT [IsThruComponent vs IsSMTComponent] p7: gap=30 collisioncheckmode=3 verticalgap=30 showdistances=FALSE
ComponentClearance ComponentClearance_THtoTH [IsThruComponent vs IsThruComponent] p8: gap=20 collisioncheckmode=3 verticalgap=30 showdistances=FALSE
ComponentClearance [All] p9: gap=15 collisioncheckmode=3 verticalgap=15 showdistances=TRUE
DiffPairsRouting 90E [All] p0 off: scope1count=1 scope1_0_kind=Board scope1_0_value=Board scope2count=1 scope2_0_kind=Board scope2_0_value=Board commentlength=70 // Protel DXP Scope 1 Expression Was: InDifferentialPair('XDSET_1_D')
DiffPairsRouting 120E [All] p0 off: scope1count=1 scope1_0_kind=Board scope1_0_value=Board scope2count=1 scope2_0_kind=Board scope2_0_value=Board commentlength=65 // Protel DXP Scope 1 Expression Was: InDifferentialPair('CANA')
DiffPairsRouting 100E_DIFF [All] p0 off: scope1count=1 scope1_0_kind=Board scope1_0_value=Board scope2count=1 scope2_0_kind=Board scope2_0_value=Board commentlength=70 // Protel DXP Scope 1 Expression Was: InDifferentialPairClass('100E')
DiffPairsRouting 90E [InDifferentialPair('XDSET_1_D')] p1: maxlimit=10 minlimit=5 mostfreqgap=10 toplayer_prefgap=5 toplayer_minwidth=4.2 toplayer_maxwidth=15 toplayer_prefwidth=4.2 midlayer1_mingap=6 midlayer1_maxgap=6 midlayer1_prefgap=6 midlayer1_minwidth=4 midlayer1_maxwidth=4 midlayer1_prefwidth=4 midlayer2_mingap=10 midlayer2_minwidth=15 midlayer2_maxwidth=15 midlayer2_prefwidth=15 midlayer3_mingap=10 midlayer3_minwidth=15 midlayer3_maxwidth=15 midlayer3_prefwidth=15 midlayer4_mingap=10 midlayer4_minwidth=15 midlayer4_maxwidth=15 midlayer4_prefwidth=15 bottomlayer_prefgap=5 bottomlayer_minwidth=4.2 bottomlayer_maxwidth=15 bottomlayer_prefwidth=4.2 maxuncoupledlength=500
DiffPairsRouting 120E [InDifferentialPair('CANA')] p2: maxlimit=10 minlimit=6.8 mostfreqgap=10 toplayer_prefgap=6.8 toplayer_minwidth=4.1 toplayer_maxwidth=15 toplayer_prefwidth=4.1 midlayer1_mingap=10 midlayer1_minwidth=15 midlayer1_maxwidth=15 midlayer1_prefwidth=15 midlayer2_mingap=10 midlayer2_minwidth=15 midlayer2_maxwidth=15 midlayer2_prefwidth=15 midlayer3_mingap=10 midlayer3_minwidth=15 midlayer3_maxwidth=15 midlayer3_prefwidth=15 midlayer4_mingap=10 midlayer4_minwidth=15 midlayer4_maxwidth=15 midlayer4_prefwidth=15 bottomlayer_prefgap=6.8 bottomlayer_minwidth=4.1 bottomlayer_maxwidth=15 bottomlayer_prefwidth=4.1 maxuncoupledlength=500
DiffPairsRouting 100E_DIFF [InDifferentialPairClass('100E')] p3: maxlimit=100 minlimit=7.7 mostfreqgap=10 toplayer_maxgap=7.7 toplayer_prefgap=7.7 toplayer_minwidth=4 toplayer_maxwidth=4 toplayer_prefwidth=4 midlayer1_mingap=8.1 midlayer1_maxgap=8.1 midlayer1_prefgap=8.1 midlayer1_minwidth=3.5 midlayer1_maxwidth=3.5 midlayer1_prefwidth=3.5 midlayer2_mingap=10 midlayer2_minwidth=15 midlayer2_maxwidth=15 midlayer2_prefwidth=15 midlayer3_mingap=10 midlayer3_minwidth=15 midlayer3_maxwidth=15 midlayer3_prefwidth=15 midlayer4_mingap=10 midlayer4_minwidth=15 midlayer4_maxwidth=15 midlayer4_prefwidth=15 bottomlayer_maxgap=7.7 bottomlayer_prefgap=7.7 bottomlayer_minwidth=4 bottomlayer_maxwidth=4 bottomlayer_prefwidth=4 maxuncoupledlength=1000
FabricationTestPointUsage TestPointUsage [All] p0: scope1count=1 scope1_0_kind=Board scope1_0_value=Board scope2count=1 scope2_0_kind=Board scope2_0_value=Board commentlength=0 valid=2 allowmultiple=FALSE
FabricationTestPointUsage TestPointUsage [All] p1: valid=2 allowmultiple=FALSE
FabricationTestpoint Testpoint [All] p0: scope1count=1 scope1_0_kind=Board scope1_0_value=Board scope2count=1 scope2_0_kind=Board scope2_0_value=Board commentlength=0 side=3 testpointundercomponent=TRUE minsize=40 maxsize=100 preferedsize=60 minholesize=0 maxholesize=40 preferedholesize=32 testpointgrid=1
FabricationTestpoint Testpoint [All] p1: side=3 testpointundercomponent=TRUE minsize=40 maxsize=100 preferedsize=60 minholesize=0 maxholesize=40 preferedholesize=32 testpointgrid=1 allowsidetop=TRUE allowsidebottom=TRUE usegrid=TRUE gridtolerance=0.01
FanoutControl Fanout_Small [All] p0 off: scope1count=1 scope1_0_kind=Board scope1_0_value=Board scope2count=1 scope2_0_kind=Board scope2_0_value=Board commentlength=84 // Protel DXP Scope 1 Expression Was: (CompPinCount < 5)   Fanout_Small (Default Rule)
FanoutControl Fanout_Default [All] p0: scope1count=1 scope1_0_kind=Board scope1_0_value=Board scope2count=1 scope2_0_kind=Board scope2_0_value=Board commentlength=30 // Fanout_Default (Default Rule)
FanoutControl Fanout_SOIC [All] p0 off: scope1count=1 scope1_0_kind=Board scope1_0_value=Board scope2count=1 scope2_0_kind=Board scope2_0_value=Board commentlength=71 // Protel DXP Scope 1 Expression Was: IsSOIC   Fanout_SOIC (Default Rule)
FanoutControl Fanout_BGA [All] p0 off: scope1count=1 scope1_0_kind=Board scope1_0_value=Board scope2count=1 scope2_0_kind=Board scope2_0_value=Board commentlength=69 // Protel DXP Scope 1 Expression Was: IsBGA   Fanout_BGA (Default Rule)
FanoutControl Fanout_LCC [All] p0 off: scope1count=1 scope1_0_kind=Board scope1_0_value=Board scope2count=1 scope2_0_kind=Board scope2_0_value=Board commentlength=69 // Protel DXP Scope 1 Expression Was: IsLCC   Fanout_LCC (Default Rule)
FanoutControl Fanout_LCC [IsLCC] p1: bgadir=Out bgaviamode=Centered fanoutstyle=Auto fanoutdirection=Alternating viagrid=1 // Fanout_LCC (Default Rule)
FanoutControl Fanout_BGA [IsBGA] p2: bgadir=Out bgaviamode=Centered fanoutstyle=Auto fanoutdirection=Alternating viagrid=1 // Fanout_BGA (Default Rule)
FanoutControl Fanout_Default [All] p4: bgadir=Out bgaviamode=Centered fanoutstyle=Auto fanoutdirection=Alternating viagrid=1 // Fanout_Default (Default Rule)
FanoutControl Fanout_Small [(CompPinCount < 5)] p5: bgadir=Out bgaviamode=Centered fanoutstyle=Auto fanoutdirection=OutThenIn viagrid=1 // Fanout_Small (Default Rule)
Height [All] p0: scope1count=1 scope1_0_kind=Board scope1_0_value=Board scope2count=1 scope2_0_kind=Board scope2_0_value=Board commentlength=0
HoleSize [All] p0: scope1count=1 scope1_0_kind=Board scope1_0_value=Board scope2count=1 scope2_0_kind=Board scope2_0_value=Board commentlength=0 absolutevalues=TRUE maxlimit=251 minlimit=7.87 maxpercent=80.000 minpercent=20.000
HoleSize [All] p1: absolutevalues=TRUE maxlimit=251 minlimit=7.87 maxpercent=80.000 minpercent=20.000
HoleToHoleClearance [All] p0: scope1count=1 scope1_0_kind=Board scope1_0_value=Board scope2count=1 scope2_0_kind=Board scope2_0_value=Board commentlength=0
LayerPairs [All] p0: scope1count=1 scope1_0_kind=Board scope1_0_value=Board scope2count=1 scope2_0_kind=Board scope2_0_value=Board commentlength=0 enforce=TRUE
MatchedLengths PRO_PROU_GPIO(11-16) [All] p0 off: scope1count=1 scope1_0_kind=Board scope1_0_value=Board scope2count=1 scope2_0_kind=Board scope2_0_value=Board commentlength=77 tolerance=7.5 amplitude=200 gap=20 style=90-Degree // Protel DXP Scope 1 Expression Was: InxSignalClass('PRO_PROU_GPIO(11-16)')
MatchedLengths PRO_PROU_GPIO(0-6) [All] p0 off: scope1count=1 scope1_0_kind=Board scope1_0_value=Board scope2count=1 scope2_0_kind=Board scope2_0_value=Board commentlength=75 tolerance=7.5 amplitude=200 gap=20 style=90-Degree // Protel DXP Scope 1 Expression Was: InxSignalClass('PRO_PROU_GPIO(0-6)')
MatchedLengths AM263_RGMII1_RX [All] p0 off: scope1count=1 scope1_0_kind=Board scope1_0_value=Board scope2count=1 scope2_0_kind=Board scope2_0_value=Board commentlength=72 tolerance=7.5 amplitude=200 gap=20 style=90-Degree // Protel DXP Scope 1 Expression Was: InxSignalClass('AM263_RGMII1_RX')
MatchedLengths AM263_RGMII1_TX [All] p0 off: scope1count=1 scope1_0_kind=Board scope1_0_value=Board scope2count=1 scope2_0_kind=Board scope2_0_value=Board commentlength=72 tolerance=7.5 amplitude=200 gap=20 style=90-Degree // Protel DXP Scope 1 Expression Was: InxSignalClass('AM263_RGMII1_TX')
MatchedLengths ICSSM_MII1_RX [All] p0 off: scope1count=1 scope1_0_kind=Board scope1_0_value=Board scope2count=1 scope2_0_kind=Board scope2_0_value=Board commentlength=70 tolerance=7.5 amplitude=200 gap=20 style=90-Degree // Protel DXP Scope 1 Expression Was: InxSignalClass('ICSSM_MII1_RX')
MatchedLengths ICSSM_MII1_TX [All] p0 off: scope1count=1 scope1_0_kind=Board scope1_0_value=Board scope2count=1 scope2_0_kind=Board scope2_0_value=Board commentlength=70 tolerance=7.5 amplitude=200 gap=20 style=90-Degree // Protel DXP Scope 1 Expression Was: InxSignalClass('ICSSM_MII1_TX')
MatchedLengths ICSSM_MII0_TX [All] p0 off: scope1count=1 scope1_0_kind=Board scope1_0_value=Board scope2count=1 scope2_0_kind=Board scope2_0_value=Board commentlength=70 tolerance=7.5 amplitude=200 gap=20 style=90-Degree // Protel DXP Scope 1 Expression Was: InxSignalClass('ICSSM_MII0_TX')
MatchedLengths ICSSM_MII0_RX [All] p0 off: scope1count=1 scope1_0_kind=Board scope1_0_value=Board scope2count=1 scope2_0_kind=Board scope2_0_value=Board commentlength=70 tolerance=7.5 amplitude=200 gap=20 style=90-Degree // Protel DXP Scope 1 Expression Was: InxSignalClass('ICSSM_MII0_RX')
MatchedLengths ETH1_TX [All] p0 off: scope1count=1 scope1_0_kind=Board scope1_0_value=Board scope2count=1 scope2_0_kind=Board scope2_0_value=Board commentlength=64 tolerance=7.5 amplitude=200 gap=20 style=90-Degree // Protel DXP Scope 1 Expression Was: InxSignalClass('ETH1_TX')
MatchedLengths ETH1_RX [All] p0 off: scope1count=1 scope1_0_kind=Board scope1_0_value=Board scope2count=1 scope2_0_kind=Board scope2_0_value=Board commentlength=64 tolerance=7.5 amplitude=200 gap=20 style=90-Degree // Protel DXP Scope 1 Expression Was: InxSignalClass('ETH1_RX')
MatchedLengths DIFF [All] p0: scope1count=1 scope1_0_kind=Board scope1_0_value=Board scope2count=1 scope2_0_kind=Board scope2_0_value=Board commentlength=0 tolerance=2 amplitude=200 gap=20 style=90-Degree
MatchedLengths "SD CARD" [All] p0 off: scope1count=1 scope1_0_kind=Board scope1_0_value=Board scope2count=1 scope2_0_kind=Board scope2_0_value=Board commentlength=61 tolerance=25 amplitude=200 gap=20 style=90-Degree // Protel DXP Scope 1 Expression Was: InxSignalClass('MMC0')
MatchedLengths QSPI [All] p0 off: scope1count=1 scope1_0_kind=Board scope1_0_value=Board scope2count=1 scope2_0_kind=Board scope2_0_value=Board commentlength=67 tolerance=25 amplitude=200 gap=20 style=90-Degree // Protel DXP Scope 1 Expression Was: InxSignalClass('QSPI_FLASH')
MatchedLengths DIFF [All] p1: tolerance=2 checknetsindiffpair=TRUE checkdiffpairvsdiffpair=FALSE checkxsignals=FALSE checkothers=FALSE
MatchedLengths QSPI [InxSignalClass('QSPI_FLASH')] p2: tolerance=25 checknetsindiffpair=FALSE checkdiffpairvsdiffpair=TRUE checkxsignals=TRUE checkothers=TRUE
MatchedLengths ETH1_RX [InxSignalClass('ETH1_RX')] p3: tolerance=7.5 checknetsindiffpair=FALSE checkdiffpairvsdiffpair=TRUE checkxsignals=TRUE checkothers=TRUE
MatchedLengths ETH1_TX [InxSignalClass('ETH1_TX')] p4: tolerance=7.5 checknetsindiffpair=FALSE checkdiffpairvsdiffpair=TRUE checkxsignals=TRUE checkothers=TRUE
MatchedLengths ICSSM_MII0_RX [InxSignalClass('ICSSM_MII0_RX')] p5: tolerance=7.5 checknetsindiffpair=FALSE checkdiffpairvsdiffpair=TRUE checkxsignals=TRUE checkothers=TRUE
MatchedLengths AM263_RGMII1_TX [InxSignalClass('AM263_RGMII1_TX')] p6: tolerance=7.5 checknetsindiffpair=FALSE checkdiffpairvsdiffpair=TRUE checkxsignals=TRUE checkothers=TRUE
MatchedLengths PRO_PROU_GPIO(0-6) [InxSignalClass('PRO_PROU_GPIO(0-6)')] p7: tolerance=7.5 checknetsindiffpair=FALSE checkdiffpairvsdiffpair=TRUE checkxsignals=TRUE checkothers=TRUE
MatchedLengths PRO_PROU_GPIO(11-16) [InxSignalClass('PRO_PROU_GPIO(11-16)')] p8: tolerance=7.5 checknetsindiffpair=FALSE checkdiffpairvsdiffpair=TRUE checkxsignals=TRUE checkothers=TRUE
MatchedLengths AM263_RGMII1_RX [InxSignalClass('AM263_RGMII1_RX')] p9: tolerance=7.5 checknetsindiffpair=FALSE checkdiffpairvsdiffpair=TRUE checkxsignals=TRUE checkothers=TRUE
MatchedLengths ICSSM_MII0_TX [InxSignalClass('ICSSM_MII0_TX')] p10: tolerance=7.5 checknetsindiffpair=FALSE checkdiffpairvsdiffpair=TRUE checkxsignals=TRUE checkothers=TRUE
MatchedLengths ICSSM_MII1_TX [InxSignalClass('ICSSM_MII1_TX')] p11: tolerance=7.5 checknetsindiffpair=FALSE checkdiffpairvsdiffpair=TRUE checkxsignals=TRUE checkothers=TRUE
MatchedLengths ICSSM_MII1_RX [InxSignalClass('ICSSM_MII1_RX')] p12: tolerance=7.5 checknetsindiffpair=FALSE checkdiffpairvsdiffpair=TRUE checkxsignals=TRUE checkothers=TRUE
MatchedLengths "SD CARD" [InxSignalClass('MMC0')] p13: tolerance=25 checknetsindiffpair=FALSE checkdiffpairvsdiffpair=TRUE checkxsignals=TRUE checkothers=TRUE
MinimumAnnularRing [All] p0: scope1count=1 scope1_0_kind=Board scope1_0_value=Board scope2count=1 scope2_0_kind=Board scope2_0_value=Board commentlength=0 minimumring=5
MinimumAnnularRing MinimumAnnularRing_ThermalPadVias [All] p0 off: scope1count=1 scope1_0_kind=Board scope1_0_value=Board scope2count=1 scope2_0_kind=Board scope2_0_value=Board commentlength=63 minimumring=5.91 // Protel DXP Scope 1 Expression Was: IsVia and InAnyComponent
MinimumAnnularRing MinimumAnnularRing_ThermalPadVias [IsVia and InAnyComponent] p1: minimumring=5.91
MinimumAnnularRing [All] p2: minimumring=5
MinimumSolderMaskSliver MinimumSolderMaskSliver_Logo [All] p0: scope1count=1 scope1_0_kind=ComponentClass scope1_0_value=Logo scope2count=1 scope2_0_kind=ComponentClass scope2_0_value=Logo commentlength=0
MinimumSolderMaskSliver MinimumSolderMaskSliver_Logo [InComponentClass('Logo') vs InComponentClass('Logo')] p1: minsoldermaskwidth=0.7
NetAntennae [All] p0: scope1count=1 scope1_0_kind=Board scope1_0_value=Board scope2count=1 scope2_0_kind=Board scope2_0_value=Board commentlength=0
PasteMaskExpansion [All] p0: scope1count=1 scope1_0_kind=Board scope1_0_value=Board scope2count=1 scope2_0_kind=Board scope2_0_value=Board commentlength=0 expansion=0
PlaneClearance [All] p0: scope1count=1 scope1_0_kind=Board scope1_0_value=Board scope2count=1 scope2_0_kind=Board scope2_0_value=Board commentlength=0 clearance=20
PlaneConnect [All] p0: scope1count=1 scope1_0_kind=Board scope1_0_value=Board scope2count=1 scope2_0_kind=Board scope2_0_value=Board commentlength=0 planeconnectstyle=Direct reliefexpansion=10 reliefentries=4 reliefconductorwidth=10 reliefairgap=10
PlaneConnect [All] p1: planeconnectstyle=Direct reliefexpansion=10 reliefentries=4 reliefconductorwidth=10 reliefairgap=10
PolygonConnect PolygonConnect_3 [All] p0 off: scope1count=1 scope1_0_kind=Board scope1_0_value=Board scope2count=1 scope2_0_kind=Board scope2_0_value=Board commentlength=71 connectstyle=Direct reliefconductorwidth=10 reliefentries=4 polygonreliefangle="90 Angle" // Protel DXP Scope 2 Expression Was: IsNamedPolygon('SIG 2-vusb_3v3')
PolygonConnect PolygonConnect_2 [All] p0 off: scope1count=1 scope1_0_kind=Board scope1_0_value=Board scope2count=1 scope2_0_kind=Board scope2_0_value=Board commentlength=81 connectstyle=Direct reliefconductorwidth=10 reliefentries=4 polygonreliefangle="90 Angle" // Protel DXP Scope 2 Expression Was: IsNamedPolygon('Top Layer-VBUS_TYPEC_5V0')
PolygonConnect PolygonConnect_1 [All] p0 off: scope1count=1 scope1_0_kind=Board scope1_0_value=Board scope2count=1 scope2_0_kind=Board scope2_0_value=Board commentlength=81 connectstyle=Direct reliefconductorwidth=10 reliefentries=4 polygonreliefangle="90 Angle" // Protel DXP Scope 2 Expression Was: IsNamedPolygon('Top Layer-VBUS_TYPEC_5V0')
PolygonConnect [All] p0: scope1count=1 scope1_0_kind=Board scope1_0_value=Board scope2count=1 scope2_0_kind=Board scope2_0_value=Board commentlength=0 connectstyle=Direct reliefconductorwidth=10 reliefentries=4 polygonreliefangle="90 Angle"
PolygonConnect PolygonConnect_3 [All vs IsNamedPolygon('SIG 2-vusb_3v3')] p1: connectstyle=Direct reliefconductorwidth=10 reliefentries=4 polygonreliefangle="90 Angle" airgapwidth=10
PolygonConnect PolygonConnect_2 [All vs IsNamedPolygon('Top Layer-VBUS_TYPEC_5V0')] p2: connectstyle=Direct reliefconductorwidth=10 reliefentries=4 polygonreliefangle="90 Angle" airgapwidth=10
PolygonConnect PolygonConnect_1 [All vs IsNamedPolygon('Top Layer-VBUS_TYPEC_5V0')] p3: connectstyle=Direct reliefconductorwidth=10 reliefentries=4 polygonreliefangle="90 Angle" airgapwidth=10
PolygonConnect [All] p4: connectstyle=Direct reliefconductorwidth=10 reliefentries=4 polygonreliefangle="90 Angle" airgapwidth=10
RoomDefinition "FLASH - NAND" [All] p0 off: scope1count=1 scope1_0_kind=Board scope1_0_value=Board scope2count=1 scope2_0_kind=Board scope2_0_value=Board commentlength=44 region_x1=28351750 region_y1=29161060 region_x2=33509230 region_y2=33727990 confinementstyle=ConfineIn // Protel DXP Scope 1 Expression Was: False
RoomDefinition PROC111_Hardware [All] p0: scope1count=1 scope1_0_kind=ComponentClass scope1_0_value=PROC111_Hardware scope2count=1 scope2_0_kind=Board scope2_0_value=Board commentlength=0 region_x1=41830000 region_y1=23160000 region_x2=48230000 region_y2=29640000 confinementstyle=ConfineIn
RoomDefinition "FLASH - NAND" [False] p1: confinementstyle=ConfineIn formatcopy=TRUE lockcomponents=FALSE outline 2143.18,1838.8 2658.92,1838.8 2658.92,1382.11 2143.18,1382.11
RoomDefinition PROC111_Hardware [InComponentClass('PROC111_Hardware')] p2: confinementstyle=ConfineIn formatcopy=TRUE lockcomponents=FALSE outline 3491,782 4131,782 4131,1430 3491,1430
RoutingCorners [All] p0: scope1count=1 scope1_0_kind=Board scope1_0_value=Board scope2count=1 scope2_0_kind=Board scope2_0_value=Board commentlength=0 cornerstyle=45-Degree minsetback=100 maxsetback=100
RoutingLayers [All] p0: scope1count=1 scope1_0_kind=Board scope1_0_value=Board scope2count=1 scope2_0_kind=Board scope2_0_value=Board commentlength=0 top layer=Automatic mid layer 1=Automatic mid layer 2=Automatic mid layer 3=Automatic mid layer 4=Automatic bottom layer=Automatic
RoutingLayers [All] p1: top layer_v5=TRUE mid layer 1_v5=TRUE mid layer 2_v5=TRUE mid layer 3_v5=FALSE mid layer 4_v5=TRUE bottom layer_v5=TRUE
RoutingPriority [All] p0: scope1count=1 scope1_0_kind=Board scope1_0_value=Board scope2count=1 scope2_0_kind=Board scope2_0_value=Board commentlength=0
RoutingTopology [All] p0: scope1count=1 scope1_0_kind=Board scope1_0_value=Board scope2count=1 scope2_0_kind=Board scope2_0_value=Board commentlength=0 topology=Shortest
RoutingVias [All] p0: scope1count=1 scope1_0_kind=Board scope1_0_value=Board scope2count=1 scope2_0_kind=Board scope2_0_value=Board commentlength=0 holewidth=8 width=18 viastyle="Through Hole" minholewidth=8 minwidth=18 maxholewidth=8 maxwidth=18
RoutingVias ThermalPadVias [All] p0 off: scope1count=1 scope1_0_kind=Board scope1_0_value=Board scope2count=1 scope2_0_kind=Board scope2_0_value=Board commentlength=63 holewidth=7.87 width=19.68 viastyle="Through Hole" minholewidth=7.87 minwidth=19.68 maxholewidth=12.99 maxwidth=23.62 // Protel DXP Scope 1 Expression Was: IsVia and InAnyComponent
RoutingVias ThermalPadVias [IsVia and InAnyComponent] p1: holewidth=7.87 width=19.68 viastyle="Through Hole" minholewidth=7.87 minwidth=19.68 maxholewidth=12.99 maxwidth=23.62
RoutingVias [All] p2: holewidth=8 width=18 viastyle="Through Hole" minholewidth=8 minwidth=18 maxholewidth=8 maxwidth=18
ShortCircuit [All] p0: scope1count=1 scope1_0_kind=Board scope1_0_value=Board scope2count=1 scope2_0_kind=Board scope2_0_value=Board commentlength=0 allowed=FALSE
SilkToBoardRegionClearance [All] p0 off: scope1count=1 scope1_0_kind=Board scope1_0_value=Board scope2count=1 scope2_0_kind=Board scope2_0_value=Board commentlength=130 // Protel DXP Scope 1 Expression Was: Not ((IsComment or IsDesignator) And (Hide <> 'False')) and not InRegion(1000,500,4000,800)
SilkToBoardRegionClearance [Not ((IsComment or IsDesignator) And (Hide <> 'False')) and not InRegion(1000,500,4000,800)] p1:
SilkToSilkClearance [All] p0: scope1count=1 scope1_0_kind=Board scope1_0_value=Board scope2count=1 scope2_0_kind=Board scope2_0_value=Board commentlength=0
SilkToSilkClearance SilkToSilkClearance_Pb-FreeLogo [All] p0 off: scope1count=1 scope1_0_kind=Board scope1_0_value=Board scope2count=1 scope2_0_kind=Board scope2_0_value=Board commentlength=120 // Protel DXP Scope 2 Expression Was: (HasFootprint('Pb-Free_Overlay_Medium') OR HasFootprint('Pb-Free_Overlay_Small'))
SilkToSilkClearance SilkToSilkClearance_Pb-FreeLogo [(HasFootprint('Pb-Free_Overlay_Medium') OR HasFootprint('Pb-Free_Overlay_Small')) vs (HasFootprint('Pb-Free_Overlay_Medium') OR HasFootprint('Pb-Free_Overlay_Small'))] p1: silktosilkclearance=0
SilkToSilkClearance [All] p2: silktosilkclearance=3.94
SilkToSolderMaskClearance "Silk to Solder Mask Opening" [All] p0: scope1count=1 scope1_0_kind=Board scope1_0_value=Board scope2count=1 scope2_0_kind=Board scope2_0_value=Board commentlength=0
SilkToSolderMaskClearance SilkToComponentPadClearance [All] p0 off: scope1count=1 scope1_0_kind=Board scope1_0_value=Board scope2count=1 scope2_0_kind=Board scope2_0_value=Board commentlength=82 // Protel DXP Scope 1 Expression Was: (IsPad or IsFill or IsRegion) and Component
SilkToSolderMaskClearance SilkToComponentPadClearance [(IsPad or IsFill or IsRegion) and Component] p1: minsilkscreentomaskgap=3.54 clearancetoexposedcopper=TRUE
SilkToSolderMaskClearance "Silk to Solder Mask Opening" [All] p2: minsilkscreentomaskgap=3 clearancetoexposedcopper=FALSE
SolderMaskExpansion [All] p0: scope1count=1 scope1_0_kind=Board scope1_0_value=Board scope2count=1 scope2_0_kind=Board scope2_0_value=Board commentlength=0 expansion=1.97
SolderMaskExpansion [All] p1: expansion=1.97 istentingtop=FALSE
UnRoutedNet [All] p0: scope1count=1 scope1_0_kind=Board scope1_0_value=Board scope2count=1 scope2_0_kind=Board scope2_0_value=Board commentlength=0
UnRoutedNet [All] p1: checkbadconnections=TRUE
UnpouredPolygon [All] p0: scope1count=1 scope1_0_kind=Board scope1_0_value=Board scope2count=1 scope2_0_kind=Board scope2_0_value=Board commentlength=0
Width "4 mil_mux" [All] p0 off: scope1count=1 scope1_0_kind=Board scope1_0_value=Board scope2count=1 scope2_0_kind=Board scope2_0_value=Board commentlength=65 maxlimit=15 minlimit=3.4 preferedwidth=10 // Protel DXP Scope 1 Expression Was: WithinRoom('FLASH - NAND')
Width 4mil_soc [All] p0 off: scope1count=1 scope1_0_kind=Board scope1_0_value=Board scope2count=1 scope2_0_kind=Board scope2_0_value=Board commentlength=69 maxlimit=20 minlimit=4 preferedwidth=15 // Protel DXP Scope 1 Expression Was: WithinRoom('PROC111_Hardware')
Width PWR [All] p0: scope1count=1 scope1_0_kind=NetClass scope1_0_value=PWR scope2count=1 scope2_0_kind=Board scope2_0_value=Board commentlength=0 maxlimit=30 minlimit=6 preferedwidth=12
Width [All] p0 off: scope1count=1 scope1_0_kind=Board scope1_0_value=Board scope2count=1 scope2_0_kind=Board scope2_0_value=Board commentlength=103 maxlimit=100 minlimit=4.75 preferedwidth=5.3 // Protel DXP Scope 1 Expression Was: not WithinRoom('PROC111_Hardware')and WithinRoom('FLASH - NAND')
Width 4mil_soc [WithinRoom('PROC111_Hardware')] p1: maxlimit=20 minlimit=4 preferedwidth=15 toplayer_prefwidth=4 midlayer1_prefwidth=4 midlayer3_minwidth=10 midlayer3_maxwidth=10 midlayer3_prefwidth=10 midlayer4_minwidth=10 midlayer4_maxwidth=10 midlayer4_prefwidth=10 bottomlayer_prefwidth=4 minimp=50.000000 maximp=50.000000 favimp=50.000000
Width "4 mil_mux" [WithinRoom('FLASH - NAND')] p2: maxlimit=15 minlimit=3.4 preferedwidth=10 toplayer_prefwidth=5.3 midlayer1_maxwidth=10 midlayer1_prefwidth=4.75 midlayer2_maxwidth=10 midlayer2_prefwidth=4.75 midlayer3_minwidth=5.3 midlayer3_maxwidth=10 midlayer4_minwidth=5.3 midlayer4_maxwidth=10 bottomlayer_prefwidth=5.3 minimp=50.000000 maximp=50.000000 favimp=50.000000
Width PWR [InNetClass('PWR')] p3: maxlimit=30 minlimit=6 preferedwidth=12 midlayer1_minwidth=8 midlayer2_minwidth=8 midlayer3_minwidth=8 midlayer4_minwidth=8 bottomlayer_minwidth=7 minimp=50.000000 maximp=50.000000 favimp=50.000000
Width [not WithinRoom('PROC111_Hardware')and WithinRoom('FLASH - NAND')] p4: maxlimit=100 minlimit=4.75 preferedwidth=5.3 toplayer_minwidth=5.3 midlayer1_prefwidth=4.75 midlayer2_minwidth=5.3 midlayer3_minwidth=5.3 midlayer4_minwidth=5.3 bottomlayer_minwidth=5.3 minimp=50.000000 maximp=50.000000 favimp=50.000000 checkconnectedcopper=TRUE
13 further rules are at their usual default settings.

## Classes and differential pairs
component class PROC171_IO_EXPANDER: C268 C269 R422 R423 R426 U63
component class PROC171_AM263P_4_EMMC: C264 C265 C266 C267 R419 R420 R421 R429 R430 R431 R432 TP35 TP36 TP37 TP38 U61 U62
net class POWER: VBUS_XDS_5V0
component class PROC171_XDS110_2: C134 C135 C136 C137 C138 C139 C140 C141 C142 C143 C144 C145 C146 C147 C148 C149 C150 C151 C152 C153 C154 C155 C156 C234 D3 DS3 R129 R130 R131 R132 R133 R134 R135 R136 R137 R138 R139 R140 R141 R142 R143 R144 R145 R259 R260 R261 R308 R309 R310 R311 R312 R324 R325 R326 R327 R399 R400 TP27 TP28 TP29 TP30 TP31 U24 U25 U26 U27 U28 Y3
component class PROC171_XDS110_1: C227 C228 C230 C231 C232 C233 J34 R251 R252 R253 TP23 TP24 TP25 TP26 U44 U45
component class PROC171_Test_Automation: C183 C184 C185 C186 C187 C188 C250 C251 C252 C262 J1 J6 L4 R21 R182 R183 R184 R185 R186 R187 R188 R191 R192 R193 R194 R195 R301 R336 R337 R338 R339 R340 R341 R342 R343 R344 R345 R346 R347 R348 R349 R350 R351 R352 R353 R354 R355 R356 R357 R358 R359 R405 R406 R407 R408 R409 R410 R411 R412 R413 R414 R415 R416 R427 R428 TP18 TP32 U36 U56 U57 U58 U59
component class PROC171_System_Power_2: C157 C158 C159 C160 C161 C162 C163 C164 C165 C166 C167 C168 C169 C170 C171 C172 C173 C174 C175 C176 C177 C178 C179 C180 C253 C254 C255 C256 L2 L3 R146 R147 R148 R149 R150 R151 R152 R153 R154 R155 R156 R157 R158 R159 R160 R161 R162 R163 R295 R296 R362 R363 R364 TP8 TP9 TP10 TP11 TP12 TP13 TP14 TP15 TP16 TP17 TP33 TP34 U29 U30 U31 U32 U55
component class PROC171_System_Power_1: C101 C102 C103 C104 C105 C106 C107 C108 C109 C110 C229 C249 D1 DS4 J5 J11 J12 L1 R32 R89 R90 R91 R92 R93 R94 R95 R97 R98 R299 R434 R439 TP3 TP4 TP5 TP6 U18 U19 U20 U21 U47
component class PROC171_Push_Buttons: C181 C182 Q1 Q2 Q3 R177 R178 R179 R180 R181 SW2 SW3 SW4 U33 U34
component class PROC171_LED: C236 C237 D2 D4 D5 D6 D7 D8 D9 D10 D11 D12 D13 D14 DS1 DS2 Q10 Q11 Q13 R257 R262 R263 R264 R265 R266 R267 R268 R269 R270 R271 R272 R273 R274 R275 R276 R277 R278 R279 R302 R303 R304 R313 R314 R315 R317 U48
component class PROC171_Ehernet_RJ45_2: C247 J8 Q7 Q8 Q9 R230 R231 R232 R233 R234 R235 R255 TP22 U40 U41
component class PROC171_Ehernet_RJ45_1: C235 J7 Q4 Q5 Q6 R224 R225 R226 R227 R228 R229 R254 TP21 U38 U39
component class PROC171_Ehernet_PHY_2: C189 C190 C191 C192 C193 C194 C195 C196 C197 C198 C199 C200 C201 C202 C203 C204 C205 C206 C207 C208 C209 C210 C263 FB5 FB6 R196 R197 R198 R199 R200 R201 R202 R203 R204 R205 R206 R207 R208 R209 R210 R211 R212 R213 R214 R215 R216 R217 R218 R219 R220 R221 R222 R223 R306 R417 R418 TP19 TP20 U37 U60 Y4
component class PROC171_Ehernet_PHY_1: C112 C113 C114 C115 C116 C117 C118 C119 C120 C121 C122 C123 C124 C125 C126 C127 C128 C129 C130 C131 C132 C133 C240 C241 C242 C270 FB3 FB4 R100 R101 R102 R103 R104 R105 R106 R107 R108 R109 R110 R111 R112 R113 R114 R115 R116 R117 R118 R119 R120 R121 R122 R123 R124 R125 R126 R127 R128 R291 R292 R293 R294 R305 R424 R425 TP7 U22 U50 U65 Y2
component class PROC171_Breakout_Headers: C211 C212 C213 C214 C215 C216 C217 C218 C219 C220 C221 C222 C223 C224 C225 C226 J15 J16 J17 J18 J23 J24 J25 J33 R236 R237 R238 R239 R240 R241 R242 R243 R244 R246 R247 R248 R249 R250 R328 R329 R330 R331 R332 R333 R334 R335 U42 U43
component class PROC171_Boosterpack_Headers: C243 C244 C245 C246 J1/J3 J2/J4 J5/J7 J6/J8 J9 J10 J13 J14 R256 R298 R300 U51 U52
component class PROC171_AM263P_Serial_Connectivity: R164 R165 R166 R167 R168 R169 R170 R171 R172 R173 R174 R175 R176 R297 R401 R402 R403 R404
component class PROC171_AM263P_8_PRU: C43 C111 C238 C239 C248 R71 R72 R73 R74 R75 R76 R77 R78 R79 R80 R81 R82 R83 R84 R85 R86 R87 R88 R96 R286 R287 R288 R289 R290 U23 U46 U49
component class PROC171_AM263P_7_RGMII_MII: C100 R61 R62 R63 R64 R65 R66 R67 R68 R69 R70 U17
component class PROC171_AM263P_6_ePWM_eQEP_FSI: C260 C261 R9 R12 R13 R46 R47 R48 R49 R50 R51 R52 R53 R54 R55 R56 R57 R58 R59 R60 R99 R280 R281 R282 R283 R284 R285 R393 R394 R395 R396 R397 R398 R433 R436 U54
component class PROC171_AM263P_3_OSPI_MMC: C66 C67 C68 C69 C70 C71 C258 C259 C271 C272 J2 R26 R27 R28 R29 R30 R31 R33 R34 R35 R36 R37 R38 R39 R40 R41 R42 R43 R361 R365 R366 R367 R368 R369 R370 R371 R372 R373 R374 R375 R376 R377 R378 R379 R380 R381 R382 R383 R384 R385 R386 R387 R388 R389 R390 R391 R392 R435 R437 R438 U7 U8 U9 U10 U11 U35 U53
component class PROC171_AM263P_2_Clock_Reset_Boot_JTAG: C57 C58 C59 C60 C61 C62 C63 C64 C65 C99 R4 R5 R6 R7 R8 R10 R11 R14 R15 R16 R17 R18 R19 R20 R22 R23 R24 R25 R245 R258 R316 R318 R319 R320 R321 R322 R323 SW1 TP1 TP2 U2 U3 U4 U5 U6 U16 Y1
component class PROC171_AM263P_1_Power: C1 C2 C3 C4 C5 C6 C7 C8 C9 C10 C11 C12 C13 C14 C15 C16 C17 C18 C19 C20 C21 C22 C23 C24 C25 C26 C27 C28 C29 C30 C31 C32 C33 C34 C35 C36 C37 C38 C39 C40 C41 C42 C44 C45 C46 C47 C48 C49 C50 C51 C52 C53 C54 C55 C56 C98 C257 FB1 FB2 R1 R2 R189 R190 R360
component class PROC171_AM263P_5_ADC_DAC: C72 C73 C74 C75 C76 C77 C78 C79 C80 C81 C82 C83 C84 C85 C86 C87 C88 C89 C90 C91 C92 C93 C94 C95 C96 C97 D15 D16 R3 R44 R45 R307 S1 S2 U1 U12 U13 U14 U15
component class PROC171_Hardware: FID1 FID2 FID3 FID4 FID5 FID6 LBL1 Logo1 Logo2 Logo3 Logo4 ZZ1 ZZ2 ZZ3 ZZ4
differential pair XDSET_1_D: +XDSET_1_D_P -XDSET_1_D_N
differential pair ETH2_TD_D: +ETH2_TD_D_P -ETH2_TD_D_N
differential pair ETH2_TD_C: +ETH2_TD_C_P -ETH2_TD_C_N
differential pair ETH2_TD_B: +ETH2_TD_B_P -ETH2_TD_B_N
differential pair ETH2_TD_A: +ETH2_TD_A_P -ETH2_TD_A_N
differential pair ETH1_TD_D: +ETH1_TD_D_P -ETH1_TD_D_N
differential pair ETH1_TD_C: +ETH1_TD_C_P -ETH1_TD_C_N
differential pair ETH1_TD_B: +ETH1_TD_B_P -ETH1_TD_B_N
differential pair ETH1_TD_A: +ETH1_TD_A_P -ETH1_TD_A_N
differential pair " ": +CANA_P -CANA_N

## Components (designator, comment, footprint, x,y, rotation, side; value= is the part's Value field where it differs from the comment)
1 "Comment" MHNP_M3_PANHEAD_PHILLIPS 200,-180 r0 top
2 "Comment" MHNP_M3_PANHEAD_PHILLIPS 7500,-180 r180 top
3 "Comment" MHNP_M3_PANHEAD_PHILLIPS 7499,5140 r180 top
4 "Comment" MHNP_M3_PANHEAD_PHILLIPS 199,5140 r0 bottom
C1 "CL10A335KP8NNNC" FP-CL10A335KP8NNNC_0603-MFG 3338.57,980.78 r270 bottom
C2 "CL10A335KP8NNNC" FP-CL10A335KP8NNNC_0603-MFG 3262.14,980.78 r270 bottom
C3 "CL10A335KP8NNNC" FP-CL10A335KP8NNNC_0603-MFG 3336.54,1363.15 r90 bottom
C4 "CL10A335KP8NNNC" FP-CL10A335KP8NNNC_0603-MFG 4200,1381.81 r0 bottom
C5 "CL10A335KP8NNNC" FP-CL10A335KP8NNNC_0603-MFG 3896.57,1501.5 r90 bottom
C6 "CL10A335KP8NNNC" FP-CL10A335KP8NNNC_0603-MFG 3619.13,1501.5 r90 bottom
C7 "GRM155R71E104KE14D" 0402 3603.63,743.75 r270 bottom
C8 "GRM155R71E104KE14D" 0402 4192.18,952.97 r0 bottom
C9 "GRM155R71E104KE14D" 0402 4193.67,890 r0 bottom
C10 "GRM155R71E104KE14D" 0402 3756.08,1499.91 r90 bottom
C11 "GRM155R71E104KE14D" 0402 3831.66,1499.91 r90 bottom
C12 "GRM155R71E104KE14D" 0402 4100.67,1498.22 r90 bottom
C13 "GRM155R71E104KE14D" 0402 4186.18,1317.07 r0 bottom
C14 "CL10A335KP8NNNC" FP-CL10A335KP8NNNC_0603-MFG 3435,824.72 r180 bottom
C15 "GRM155R71E104KE14D" 0402 3553.63,743.75 r270 bottom
C16 "GRM155R71E104KE14D" 0402 3688.87,1499.91 r90 bottom
C17 "GRM155R71E104KE14D" 0402 4190.85,1013.32 r0 bottom
C18 "GRM155R71E104KE14D" 0402 4186.18,1254.06 r0 bottom
C19 "GRM033C80J105ME05D" FP-GRM033C80J105ME05D_0201-MFG 3956.58,1193.07 r90 bottom
C20 "GRM033C80J105ME05D" FP-GRM033C80J105ME05D_0201-MFG 3445.84,994.56 r90 bottom
C21 "GRM033C80J105ME05D" FP-GRM033C80J105ME05D_0201-MFG 3443.33,1355.85 r270 bottom
C22 "GRM033C80J105ME05D" FP-GRM033C80J105ME05D_0201-MFG 3916.09,1115.08 r0 bottom
C23 "CL10A335KP8NNNC" FP-CL10A335KP8NNNC_0603-MFG 4107.94,624.92 r0 bottom
C24 "GRM155R71E104KE14D" 0402 4100.96,554.26 r0 bottom
C25 "CL10A335KP8NNNC" FP-CL10A335KP8NNNC_0603-MFG 3875,540.45 r180 bottom
C26 "GRM155R71E104KE14D" 0402 3875.31,608.97 r180 bottom
C27 "GRM155R71E104KE14D" 0402 3875.31,658.97 r180 bottom
C28 "GRM155R71E104KE14D" 0402 3875.31,708.97 r180 bottom
C29 "GRM033C80J105ME05D" FP-GRM033C80J105ME05D_0201-MFG 3445.84,1108.91 r270 bottom
C30 "GRM033C80J105ME05D" FP-GRM033C80J105ME05D_0201-MFG 3815,1273.75 r180 bottom
C31 "GRM033C80J105ME05D" FP-GRM033C80J105ME05D_0201-MFG 3814.85,1239.57 r180 bottom
C32 "GRM033C80J105ME05D" FP-GRM033C80J105ME05D_0201-MFG 3445.84,1234.32 r90 bottom
C33 "GRM188Z71A475ME15D" 0603 3738.88,569.08 r0 bottom
C34 "GRM155R71E104KE14D" 0402 3736.38,658.97 r0 bottom
C35 "GRM155R71E104KE14D" 0402 4139.44,717.13 r270 bottom
C36 "GRM155R71E104KE14D" 0402 3736.38,708.97 r0 bottom
C37 "GRM155R71E104KE14D" 0402 3739.61,493 r0 bottom
C38 "GRM155R71E104KE14D" 0402 3531.39,509.65 r90 bottom
C39 "GRM033C80J105ME05D" FP-GRM033C80J105ME05D_0201-MFG 3956.58,973 r90 bottom
C40 "GRM033C80J105ME05D" FP-GRM033C80J105ME05D_0201-MFG 3395.84,1108.91 r270 bottom
C41 "GRM033C80J105ME05D" FP-GRM033C80J105ME05D_0201-MFG 3673,1193.07 r90 bottom
C42 "GRM033C80J105ME05D" FP-GRM033C80J105ME05D_0201-MFG 3412.37,1355.85 r270 bottom
C43 "GRM155R71E104KE14D" 0402 5975,914.8 r180 top
C44 "GRM033C80J105ME05D" FP-GRM033C80J105ME05D_0201-MFG 3395.84,1234.06 r90 bottom
C45 "GRM033C80J105ME05D" FP-GRM033C80J105ME05D_0201-MFG 3395.84,994.56 r90 bottom
C46 "GRM033C80J105ME05D" FP-GRM033C80J105ME05D_0201-MFG 3693.17,1115.1 r270 bottom
C47 "GRM033C80J105ME05D" FP-GRM033C80J105ME05D_0201-MFG 3956.58,1060.9 r90 bottom
C48 "GRM155R71E104KE14D" 0402 3287.47,633.24 r270 top
C49 "GRM033Z71C104KE14D" 0201 3477,1360 r90 bottom
C50 "GRM033Z71C104KE14D" 0201 3814.85,946.1 r90 bottom
C51 "GRM033Z71C104KE14D" 0201 3892.96,1257.37 r0 bottom
C52 "CL10A335KP8NNNC" FP-CL10A335KP8NNNC_0603-MFG 3310.82,1114.16 r90 bottom
C53 "CL10A335KP8NNNC" FP-CL10A335KP8NNNC_0603-MFG 3274.66,1362.64 r90 bottom
C54 "GRM033Z71C104KE14D" 0201 3654.78,1115.1 r90 bottom
C55 "GRM033Z71C104KE14D" 0201 3992.66,1115.08 r180 bottom
C56 "GRM033Z71C104KE14D" 0201 3673,1004.38 r90 bottom
C57 "GRM155R71E104KE14D" 0402 2162.4,1279.45 r180 top
C58 "GJM1555C1H120JB01D" FP-GJM1555C1H120JB01D_0402-MFG 3356.21,748.05 r90 top
C59 "GJM1555C1H120JB01D" FP-GJM1555C1H120JB01D_0402-MFG 3355,812.47 r90 top
C60 "GRM155R71E104KE14D" 0402 3215,418.33 r0 top
C61 "GRM155R71E104KE14D" 0402 3653.69,81.97 r90 bottom
C62 "GRM155R71E104KE14D" 0402 3713.69,81.97 r90 bottom
C63 "GRM1555C1E103JE01D" FP-GRM1555C1E103JE01D_0402-MFG 2207.84,767.39 r270 top
C64 "GRM155R71E104KE14D" 0402 2017.57,746.48 r270 top
C65 "GRM155R71E104KE14D" 0402 1939.22,1024.86 r0 top
C66 "885012105010" 0402 2800.7,1120.06 r90 bottom
C67 "GRM188Z71C475KE21D" 0603 611.03,672.69 r90 top
C68 "CL10A335KP8NNNC" FP-CL10A335KP8NNNC_0603-MFG 924.76,669.66 r90 top
C69 "GRM155R71E104KE14D" 0402 862.1,661.79 r90 top
C70 "GRM155R71E104KE14D" 0402 1974.81,1395.84 r180 bottom
C71 "GRM155R71E104KE14D" 0402 587.8,785.43 r180 bottom
C72 "GRM1555C1H331JA01D" 0402 1745,571.95 r90 top
C73 "GRM1555C1H331JA01D" 0402 1805,571.95 r90 top
C74 "GRM1555C1H331JA01D" 0402 1865,571.95 r90 top
C75 "GRM1555C1H331JA01D" 0402 1924,571.95 r90 top
C76 "GRM188Z71A475ME15D" 0603 3713.17,668.93 r270 top
C77 "GRM188Z71A475ME15D" 0603 3861.33,668.93 r270 top
C78 "GRM155R71E104KE14D" 0402 3720.36,789.94 r0 bottom
C79 "GRM155R71E104KE14D" 0402 3844.81,789.94 r0 bottom
C80 "GRM155R71E104KE14D" 0402 3948.62,789.94 r180 bottom
C81 "GRM1555C1H331JA01D" 0402 2090,572.47 r90 top
C82 "GRM1555C1H331JA01D" 0402 2150,572.47 r90 top
C83 "GRM1555C1H331JA01D" 0402 2210,572.47 r90 top
C84 "GRM1555C1H331JA01D" 0402 2269,572.47 r90 top
C85 "GRM1555C1H331JA01D" 0402 4747.11,585.15 r90 top
C86 "GRM1555C1H331JA01D" 0402 4802.11,585.15 r90 top
C87 "GRM1555C1H331JA01D" 0402 4856.7,585.15 r90 top
C88 "GRM1555C1H331JA01D" 0402 4911.11,585.15 r90 top
C89 "GRM188Z71A475ME15D" 0603 3015,660 r90 bottom
C90 "GRM155R71E104KE14D" 0402 3595,594.91 r270 bottom
C91 "GRM155R71E104KE14D" 0402 3590,595 r270 top
C92 "GRM1555C1H331JA01D" 0402 4965,586 r90 top
C93 "GRM1555C1H331JA01D" 0402 5017.97,585.3 r90 top
C94 "GRM1555C1H331JA01D" 0402 5073,585.3 r90 top
C95 "GRM1555C1H331JA01D" 0402 5128.54,585.3 r90 top
C96 "GRM1555C1H331JA01D" 0402 4339.72,549.93 r90 top
C97 "GRM1555C1H331JA01D" 0402 2010,571.38 r90 top
C98 "GRM155R71E104KE14D" 0402 3494.98,1177.95 r180 bottom
C99 "GRM155R71E104KE14D" 0402 5570,487.03 r180 bottom
C100 "GRM155R71E104KE14D" 0402 4735,1152.06 r0 bottom
C101 "GRM188R72A104KA35D" 0603 420.79,454.11 r180 top
C102 "GRM32EC72A106KE05L" FP-GRM32EC72A106KE05L_1210-MFG 1160.42,558.6 r270 top
C103 "GRM188R72A104KA35J" 0603 1269.1,548.98 r90 top
C104 "GRM32EC72A106KE05L" FP-GRM32EC72A106KE05L_1210-MFG 1375.6,579.93 r270 top
C105 "GRM32EC72A106KE05L" FP-GRM32EC72A106KE05L_1210-MFG 1488.89,593.27 r270 bottom
C106 "GRM188R72A104KA35D" 0603 1579.67,844.07 r90 top
C107 "GRM32EC72A106KE05L" FP-GRM32EC72A106KE05L_1210-MFG 1757.45,759.21 r270 bottom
